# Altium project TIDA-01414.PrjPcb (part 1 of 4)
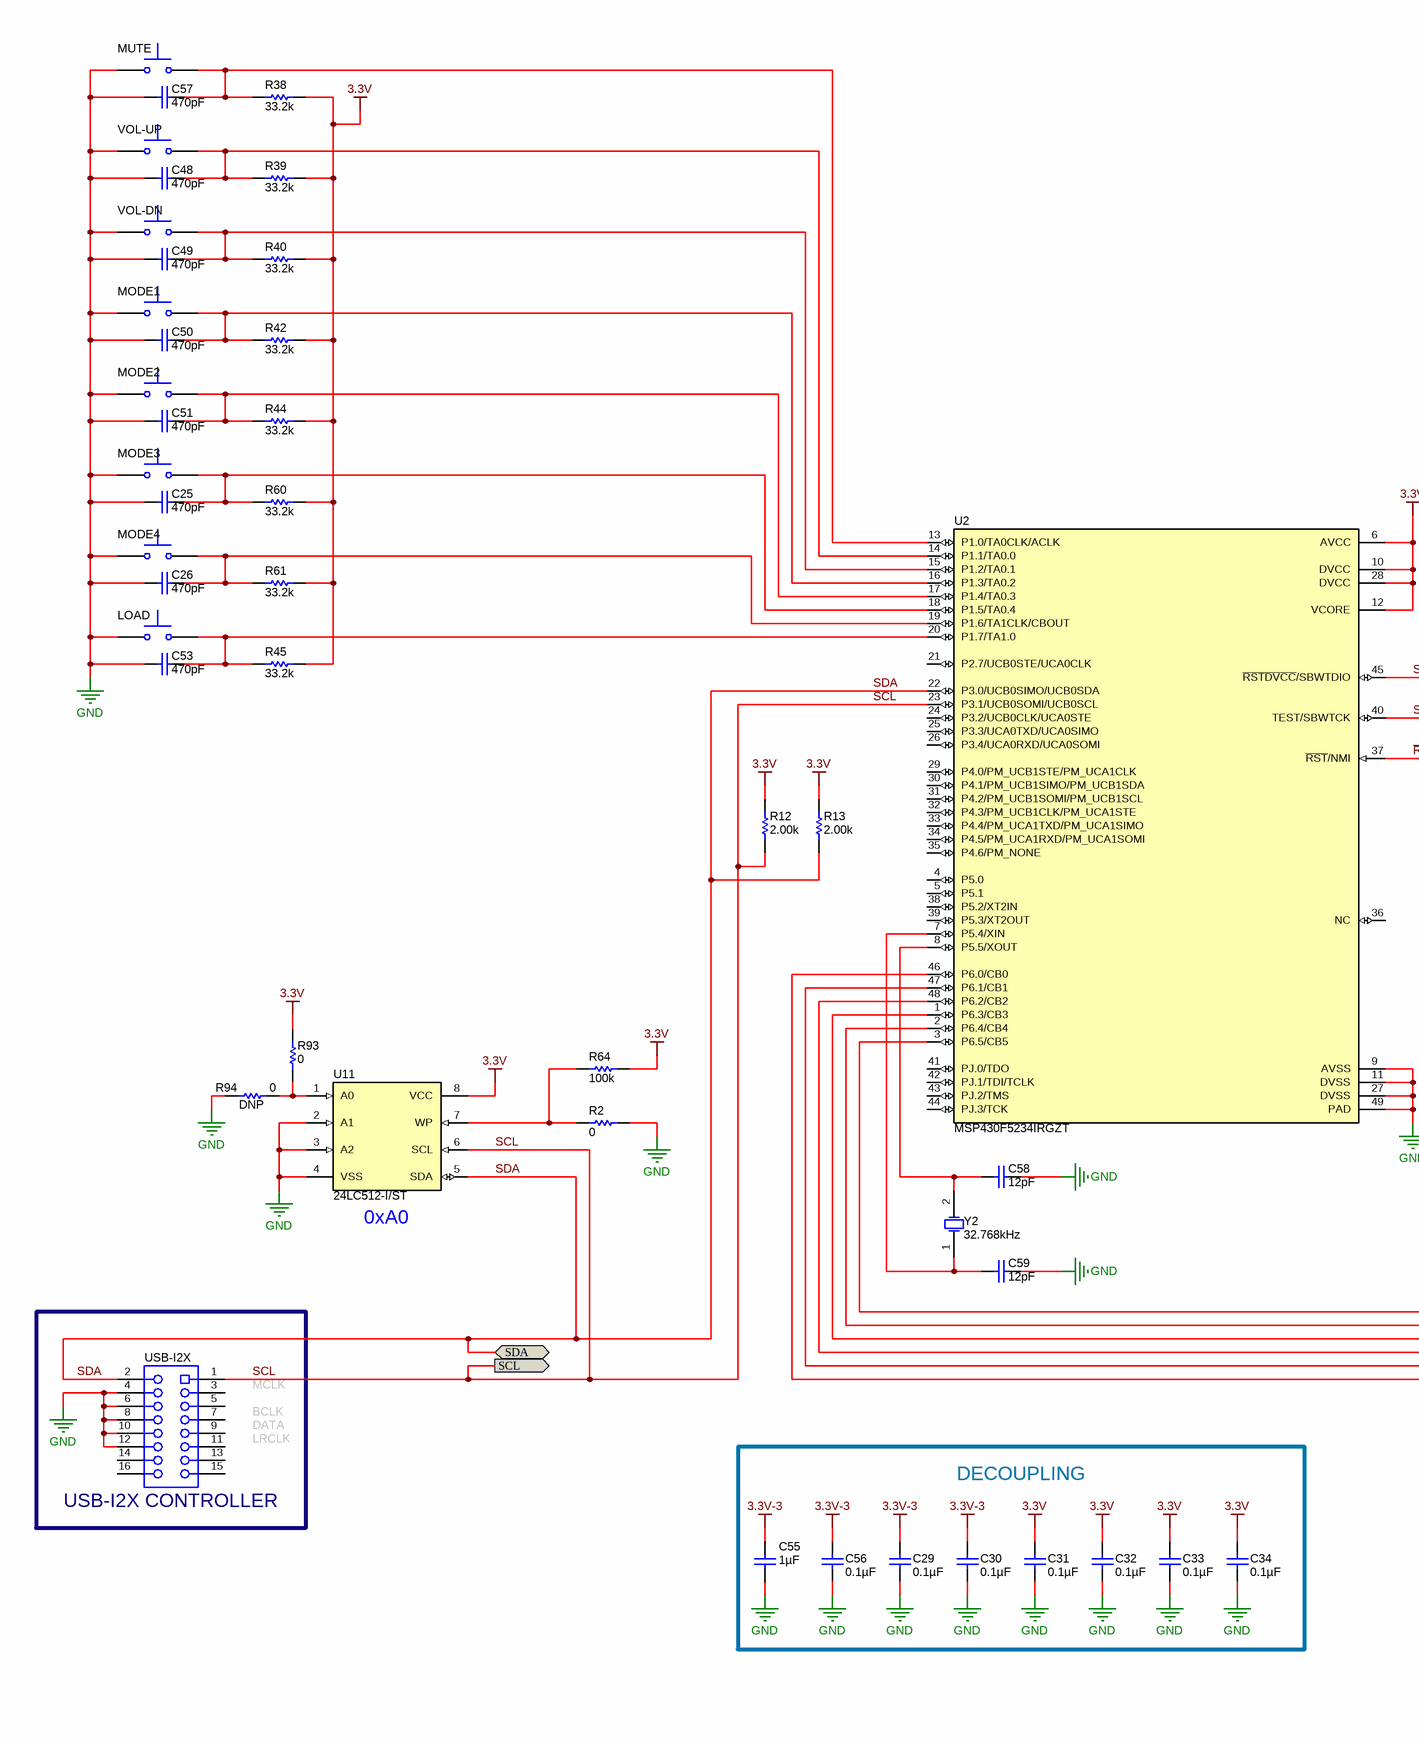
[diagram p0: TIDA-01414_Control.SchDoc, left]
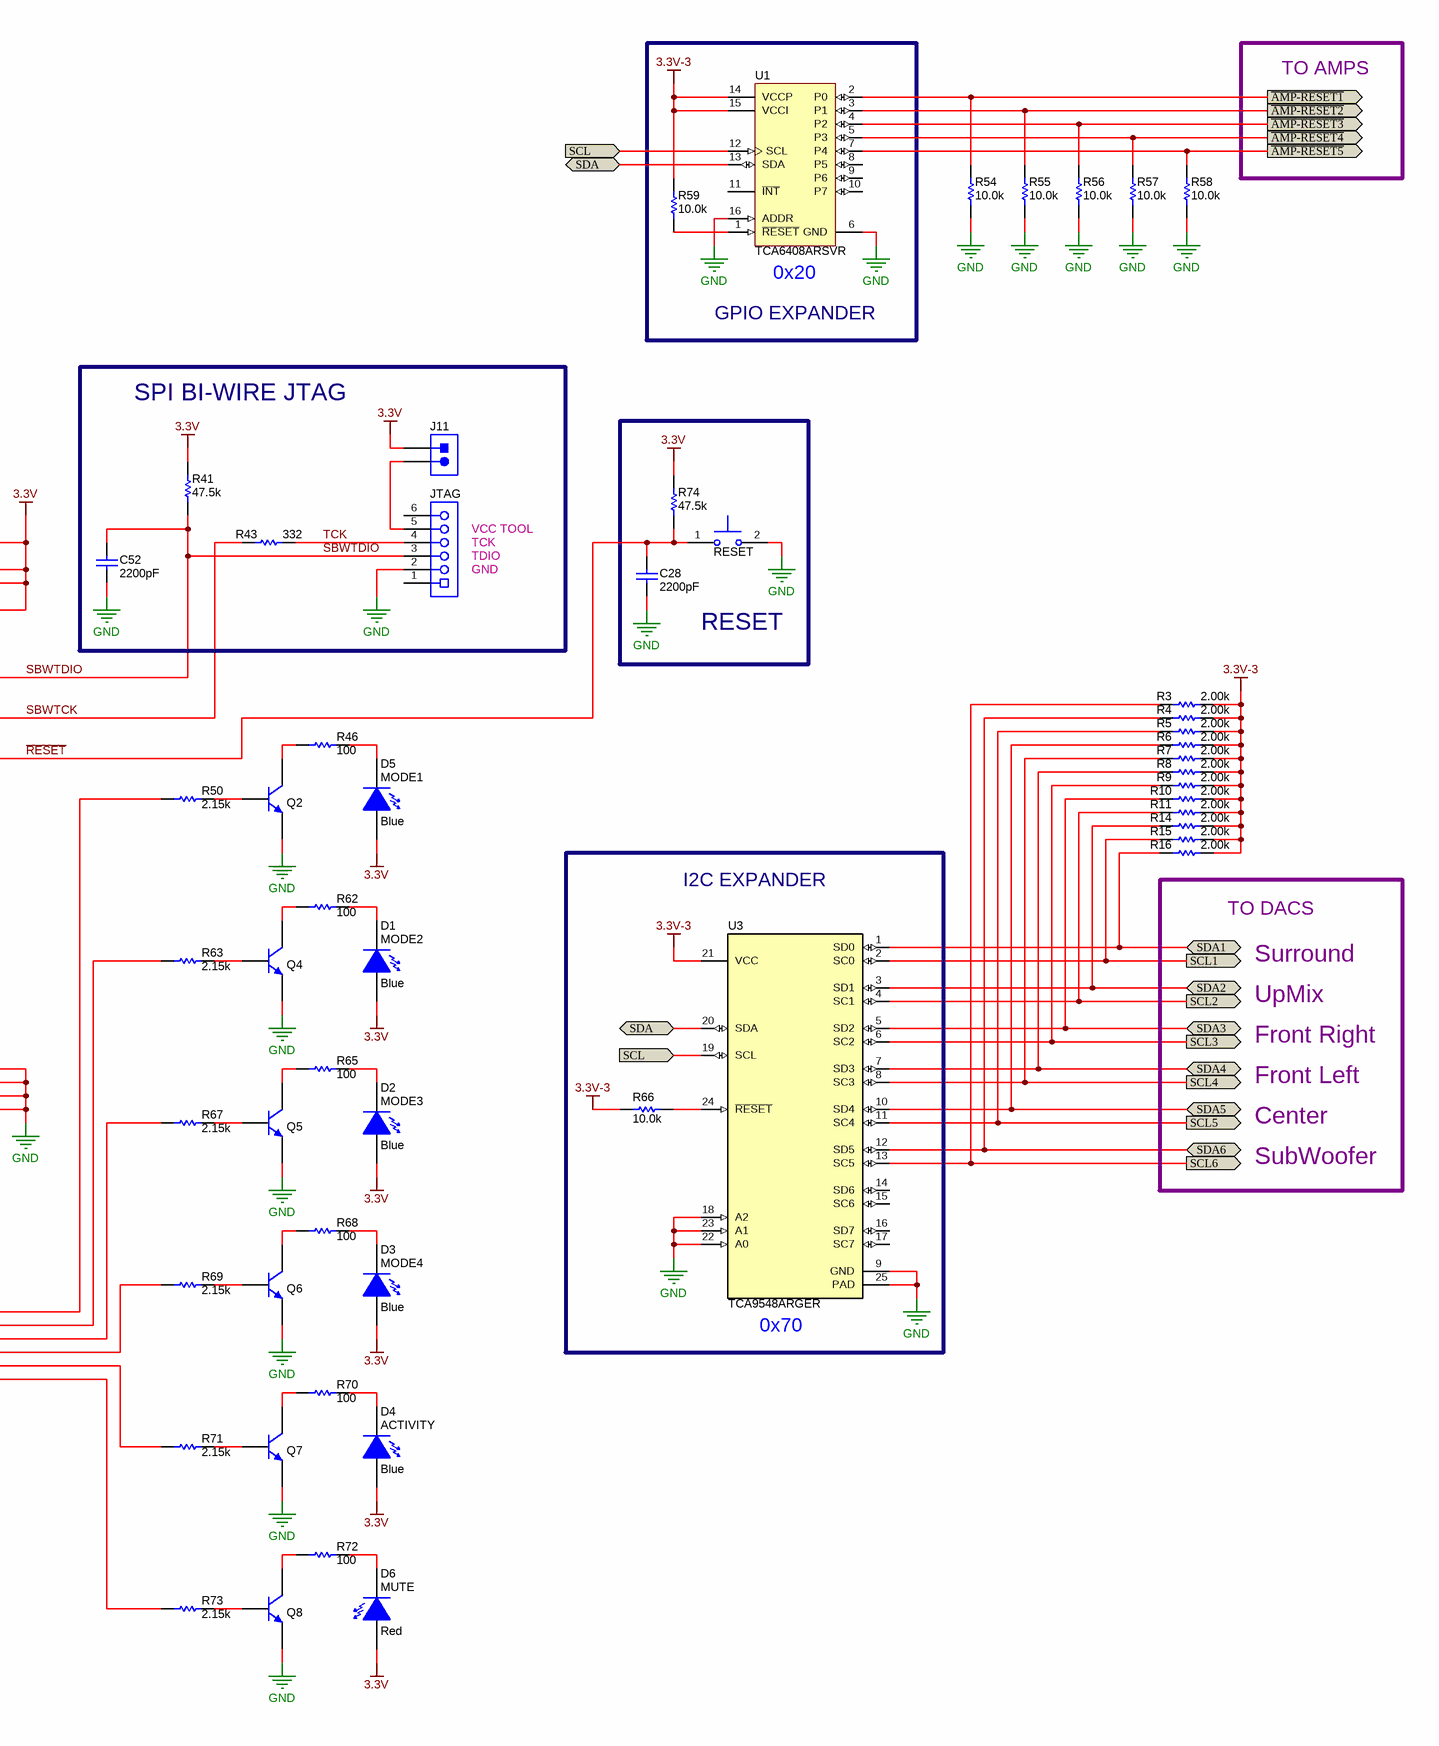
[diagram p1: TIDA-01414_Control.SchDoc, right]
CopyrightYear: 2017; EVM_Orderable: NA; PCB_Layout: LDN; PCB_Rev: E1; PRJ_Customer: Public Release; PRJ_Engineer: MATT BEARDSWORTH; PRJ_Number: TIDA-01414; PRJ_Title: TPA3244 Dolby Atmos SoundBar Reference Design; SCH_Rev: E1; TechSupport: http://www.ti.com/support; TID: TIDA-01414
12 sheets, 841 parts. Net scope: flat (ports and power ports of the same name join across sheets).
Board file: TIDA-01414.PcbDoc
Sheets:
  TIDA-01414_Control.SchDoc
  TIDA-01414_ClockDrivers.SchDoc
  TIDA-01414_SurroundChannel.SchDoc
  TIDA-01414_UpChannel.SchDoc
  TIDA-01414_FrontRightChannel.SchDoc
  TIDA-01414_FrontLeftChannel.SchDoc
  TIDA-01414_CenterChannel.SchDoc
  TIDA-01414_SubWooferChannel.SchDoc
  TIDA-01414_PowerSupplies.SchDoc
  TIDA-01414_Analog-Input_DaughterCard.SchDoc
  TIDA-01414_TID_Hardware.SchDoc
  TIDA-01414_CableAssemblies.SchDoc

## Sheet TIDA-01414_Control.SchDoc: MSP540 IO
size 538 x 342 mm; Date: Not shown in title block; ApprovedBy: Not shown in title block; CheckedBy: Not shown in title block; Author: Not shown in title block; CompanyName: Not shown in title block; DrawnBy: LDN; Engineer: Not shown in title block; Organization: Not shown in title block; Address1: Not shown in title block; Address2: Not shown in title block; Address3: Not shown in title block; Address4: Not shown in title block; DocumentNumber: 1; Revision: Use project parameter SCH_Rev; SheetNumber: 1; SheetTotal: 12; PageSetup: Record=PageOptions¦CenterHorizontal=True¦CenterVertical=True¦PrintScale=1.00¦XCorrection=1.00¦YCorrection=1.00¦PrintKind=0¦BorderSize=5000000¦LeftOffset=0¦BottomOffset=0¦Orientation=2¦PaperLength=1000¦PaperWidth=1000¦Scale=100¦PaperSource=15¦PrintQuality=600¦MediaType=1¦DitherType=10¦PaperKind=Letter¦PrintScaleMode=1

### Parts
C25  ValueDisplayed: 470pF  [0402L]  (hidden comment: GRM1555C1E471JA01D)
C26  ValueDisplayed: 470pF  [0402L]  (hidden comment: GRM1555C1E471JA01D)
C28  ValueDisplayed: 2200pF  [0603L]  (hidden comment: 885012206036)
C29  ValueDisplayed: 0.1µF  [0402L]  (hidden comment: GRM155R71A104KA01D)
C30  ValueDisplayed: 0.1µF  [0402L]  (hidden comment: GRM155R71A104KA01D)
C31  ValueDisplayed: 0.1µF  [0402L]  (hidden comment: GRM155R71A104KA01D)
C32  ValueDisplayed: 0.1µF  [0402L]  (hidden comment: GRM155R71A104KA01D)
C33  ValueDisplayed: 0.1µF  [0402L]  (hidden comment: GRM155R71A104KA01D)
C34  ValueDisplayed: 0.1µF  [0402L]  (hidden comment: GRM155R71A104KA01D)
C48  ValueDisplayed: 470pF  [0402L]  (hidden comment: GRM1555C1E471JA01D)
C49  ValueDisplayed: 470pF  [0402L]  (hidden comment: GRM1555C1E471JA01D)
C50  ValueDisplayed: 470pF  [0402L]  (hidden comment: GRM1555C1E471JA01D)
C51  ValueDisplayed: 470pF  [0402L]  (hidden comment: GRM1555C1E471JA01D)
C52  ValueDisplayed: 2200pF  [0603L]  (hidden comment: 885012206036)
C53  ValueDisplayed: 470pF  [0402L]  (hidden comment: GRM1555C1E471JA01D)
C55  ValueDisplayed: 1µF  [0402L]  (hidden comment: C1005X5R0J105M050BB)
C56  ValueDisplayed: 0.1µF  [0402L]  (hidden comment: GRM155R71A104KA01D)
C57  ValueDisplayed: 470pF  [0402L]  (hidden comment: GRM1555C1E471JA01D)
C58  ValueDisplayed: 12pF  [0402L]  (hidden comment: GRM1555C1H120JA01D)
C59  ValueDisplayed: 12pF  [0402L]  (hidden comment: GRM1555C1H120JA01D)
D1  MODE2  value Blue  [LED_SMLP12_BLUE]
D2  MODE3  value Blue  [LED_SMLP12_BLUE]
D3  MODE4  value Blue  [LED_SMLP12_BLUE]
D4  ACTIVITY  value Blue  [LED_SMLP12_BLUE]
D5  MODE1  value Blue  [LED_SMLP12_BLUE]
D6  MUTE  value Red  [LED_LTST-C190_Red]
J11  PBC02SAAN  [Sullins_PBC02SAAN]  (value not drawn)
JTAG  851-43-006-10-001000  [Mill-Max_851-XX-006-10-001000]  (value not drawn)
LOAD  (no value)  [SW_TL1015AF160QG]
MODE1  (no value)  [SW_TL1015AF160QG]
MODE2  (no value)  [SW_TL1015AF160QG]
MODE3  (no value)  [SW_TL1015AF160QG]
MODE4  (no value)  [SW_TL1015AF160QG]
MUTE  (no value)  [SW_TL1015AF160QG]
Q2  MMBT2222A  [SOT-23]  (value not drawn)
Q4  MMBT2222A  [SOT-23]  (value not drawn)
Q5  MMBT2222A  [SOT-23]  (value not drawn)
Q6  MMBT2222A  [SOT-23]  (value not drawn)
Q7  MMBT2222A  [SOT-23]  (value not drawn)
Q8  MMBT2222A  [SOT-23]  (value not drawn)
R2  ValueDisplayed: 0  [0603L]  (hidden comment: CRCW06030000Z0EA)
R3  ValueDisplayed: 2.00k  [0402L]  (hidden comment: ERJ-2RKF2001X)
R4  ValueDisplayed: 2.00k  [0402L]  (hidden comment: ERJ-2RKF2001X)
R5  ValueDisplayed: 2.00k  [0402L]  (hidden comment: ERJ-2RKF2001X)
R6  ValueDisplayed: 2.00k  [0402L]  (hidden comment: ERJ-2RKF2001X)
R7  ValueDisplayed: 2.00k  [0402L]  (hidden comment: ERJ-2RKF2001X)
R8  ValueDisplayed: 2.00k  [0402L]  (hidden comment: ERJ-2RKF2001X)
R9  ValueDisplayed: 2.00k  [0402L]  (hidden comment: ERJ-2RKF2001X)
R10  ValueDisplayed: 2.00k  [0402L]  (hidden comment: ERJ-2RKF2001X)
R11  ValueDisplayed: 2.00k  [0402L]  (hidden comment: ERJ-2RKF2001X)
R12  ValueDisplayed: 2.00k  [0402L]  (hidden comment: ERJ-2RKF2001X)
R13  ValueDisplayed: 2.00k  [0402L]  (hidden comment: ERJ-2RKF2001X)
R14  ValueDisplayed: 2.00k  [0402L]  (hidden comment: ERJ-2RKF2001X)
R15  ValueDisplayed: 2.00k  [0402L]  (hidden comment: ERJ-2RKF2001X)
R16  ValueDisplayed: 2.00k  [0402L]  (hidden comment: ERJ-2RKF2001X)
R38  ValueDisplayed: 33.2k  [0402L]  (hidden comment: CRCW040233K2FKED)
R39  ValueDisplayed: 33.2k  [0402L]  (hidden comment: CRCW040233K2FKED)
R40  ValueDisplayed: 33.2k  [0402L]  (hidden comment: CRCW040233K2FKED)
R41  ValueDisplayed: 47.5k  [0402L]  (hidden comment: CRCW040247K5FKED)
R42  ValueDisplayed: 33.2k  [0402L]  (hidden comment: CRCW040233K2FKED)
R43  ValueDisplayed: 332  [0402L]  (hidden comment: CRCW0402332RFKED)
R44  ValueDisplayed: 33.2k  [0402L]  (hidden comment: CRCW040233K2FKED)
R45  ValueDisplayed: 33.2k  [0402L]  (hidden comment: CRCW040233K2FKED)
R46  ValueDisplayed: 100  [0402L]  (hidden comment: ERJ-2RKF1000X)
R50  ValueDisplayed: 2.15k  [0402L]  (hidden comment: CRCW04022K15FKED)
R54  ValueDisplayed: 10.0k  [0603L]  (hidden comment: CRCW060310K0FKEA)
R55  ValueDisplayed: 10.0k  [0603L]  (hidden comment: CRCW060310K0FKEA)
R56  ValueDisplayed: 10.0k  [0603L]  (hidden comment: CRCW060310K0FKEA)
R57  ValueDisplayed: 10.0k  [0603L]  (hidden comment: CRCW060310K0FKEA)
R58  ValueDisplayed: 10.0k  [0603L]  (hidden comment: CRCW060310K0FKEA)
R59  value 10.0k  [0402L]  (hidden comment: CRCW040210K0FKED)
R60  ValueDisplayed: 33.2k  [0402L]  (hidden comment: CRCW040233K2FKED)
R61  ValueDisplayed: 33.2k  [0402L]  (hidden comment: CRCW040233K2FKED)
R62  ValueDisplayed: 100  [0402L]  (hidden comment: ERJ-2RKF1000X)
R63  ValueDisplayed: 2.15k  [0402L]  (hidden comment: CRCW04022K15FKED)
R64  value 100k  [0402L]  (hidden comment: CRCW0402100KFKED)
R65  ValueDisplayed: 100  [0402L]  (hidden comment: ERJ-2RKF1000X)
R66  ValueDisplayed: 10.0k  [0603L]  (hidden comment: CRCW060310K0FKEA)
R67  ValueDisplayed: 2.15k  [0402L]  (hidden comment: CRCW04022K15FKED)
R68  ValueDisplayed: 100  [0402L]  (hidden comment: ERJ-2RKF1000X)
R69  ValueDisplayed: 2.15k  [0402L]  (hidden comment: CRCW04022K15FKED)
R70  ValueDisplayed: 100  [0402L]  (hidden comment: ERJ-2RKF1000X)
R71  ValueDisplayed: 2.15k  [0402L]  (hidden comment: CRCW04022K15FKED)
R72  ValueDisplayed: 100  [0402L]  (hidden comment: ERJ-2RKF1000X)
R73  ValueDisplayed: 2.15k  [0402L]  (hidden comment: CRCW04022K15FKED)
R74  ValueDisplayed: 47.5k  [0402L]  (hidden comment: CRCW040247K5FKED)
R93  ValueDisplayed: 0  [0603L]  (hidden comment: CRCW06030000Z0EA)
R94  DNP  ValueDisplayed: 0  [0603L]
RESET  TL1015AF160QG  [SW_TL1015AF160QG]  (value not drawn)
U1  TCA6408ARSVR  [RSV0016A]
U2  MSP430F5234IRGZT  [RGZ0048B]
U3  TCA9548ARGER  [RGE0024C]
U11  24LC512-I/ST  [TSSOP-8]
USB-I2X  PPPC082LFBN-RC  [Sullins_xPxC082LFBN]  (value not drawn)
VOL-DN  (no value)  [SW_TL1015AF160QG]
VOL-UP  (no value)  [SW_TL1015AF160QG]
Y2  Frequency: 32.768kHz  [XTAL_NX3215SA]  (hidden comment: NX3215SA-32.768K-STD-MUA-8)

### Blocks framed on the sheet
SPI BI-WIRE JTAG: C52 J11 JTAG R41 R43
RESET: C28 R74 RESET
USB-I2X CONTROLLER: USB-I2X
DECOUPLING: C29-C34 C55 C56

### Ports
SCL1 (out), SCL2 (out), SCL3 (out), SCL4 (out), SCL5 (out), SCL6 (out), SCL (in), SCL (out), SDA1 (bidir), SDA2 (bidir), SDA3 (bidir), SDA4 (bidir), SDA5 (bidir), SDA6 (bidir), SDA (bidir), ~{AMP-RESET1} (out), ~{AMP-RESET2} (out), ~{AMP-RESET3} (out), ~{AMP-RESET4} (out), ~{AMP-RESET5} (out)

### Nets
3.3V: C31.2 C32.2 C33.2 C34.2 D1.1(A) D2.1(A) D3.1(A) D4.1(A) D5.1(A) D6.1(A) J11.1 R12.1 R13.1 R38.1 R39.1 R40.1 R41.2 R42.1 R44.1 R45.1 R60.1 R61.1 R64.2 R74.2 R93.2 U2.6(AVCC) U2.10(DVCC) U2.12(VCORE) U2.28(DVCC) U11.8(VCC)
3.3V-3: C29.2 C30.2 C55.2 C56.2 R3.2 R4.2 R5.2 R6.2 R7.2 R8.2 R9.2 R10.2 R11.2 R14.2 R15.2 R16.2 R59.1 R66.2 U1.14(VCCP) U1.15(VCCI) U3.21(VCC)
GND: C25.2 C26.2 C28.1 C29.1 C30.1 C31.1 C32.1 C33.1 C34.1 C48.2 C49.2 C50.2 C51.2 C52.1 C53.2 C55.1 C56.1 C57.2 C58.1 C59.1 JTAG.2 LOAD.1 MODE1.1 MODE2.1 MODE3.1 MODE4.1 MUTE.1 Q2.2(E) Q4.2(E) Q5.2(E) Q6.2(E) Q7.2(E) Q8.2(E) R2.2 R54.2 R55.2 R56.2 R57.2 R58.2 R94.2 RESET.2 U1.6(GND) U1.16(ADDR) U2.9(AVSS) U2.11(DVSS) U2.27(DVSS) U2.49(PAD) U3.9(GND) U3.18(A2) U3.22(A0) U3.23(A1) U3.25(PAD) U11.2(A1) U11.3(A2) U11.4(VSS) USB-I2X.4 USB-I2X.6 USB-I2X.8 USB-I2X.10 USB-I2X.12 VOL-DN.1 VOL-UP.1
~{AMP-RESET1}: R54.1 U1.2(P0) ; port ~{AMP-RESET1}
~{AMP-RESET2}: R55.1 U1.3(P1) ; port ~{AMP-RESET2}
~{AMP-RESET3}: R56.1 U1.4(P2) ; port ~{AMP-RESET3}
~{AMP-RESET4}: R57.1 U1.5(P3) ; port ~{AMP-RESET4}
~{AMP-RESET5}: R58.1 U1.7(P4) ; port ~{AMP-RESET5}
~{RESET}: C28.2 R74.1 RESET.1 U2.37(~{RST}/NMI)
SBWTCK: R43.1 U2.40(TEST/SBWTCK)
SBWTDIO: C52.2 JTAG.3 R41.1 U2.45(~{RSTDVCC}/SBWTDIO)
SCL: R12.2 U1.12(SCL) U2.23(P3.1/UCB0SOMI/UCB0SCL) U3.19(SCL) U11.6(SCL) USB-I2X.1 ; port SCL
SCL1: R15.1 U3.2(SC0) ; port SCL1
SCL2: R11.1 U3.4(SC1) ; port SCL2
SCL3: R9.1 U3.6(SC2) ; port SCL3
SCL4: R7.1 U3.8(SC3) ; port SCL4
SCL5: R5.1 U3.11(SC4) ; port SCL5
SCL6: R3.1 U3.13(SC5) ; port SCL6
SDA: R13.2 U1.13(SDA) U2.22(P3.0/UCB0SIMO/UCB0SDA) U3.20(SDA) U11.5(SDA) USB-I2X.2 ; port SDA
SDA1: R16.1 U3.1(SD0) ; port SDA1
SDA2: R14.1 U3.3(SD1) ; port SDA2
SDA3: R10.1 U3.5(SD2) ; port SDA3
SDA4: R8.1 U3.7(SD3) ; port SDA4
SDA5: R6.1 U3.10(SD4) ; port SDA5
SDA6: R4.1 U3.12(SD5) ; port SDA6
TCK: JTAG.4 R43.2
NetC25_1: C25.1 MODE3.2 R60.2 U2.18(P1.5/TA0.4)
NetC26_1: C26.1 MODE4.2 R61.2 U2.19(P1.6/TA1CLK/CBOUT)
NetC48_1: C48.1 R39.2 U2.14(P1.1/TA0.0) VOL-UP.2
NetC49_1: C49.1 R40.2 U2.15(P1.2/TA0.1) VOL-DN.2
NetC50_1: C50.1 MODE1.2 R42.2 U2.16(P1.3/TA0.2)
NetC51_1: C51.1 MODE2.2 R44.2 U2.17(P1.4/TA0.3)
NetC53_1: C53.1 LOAD.2 R45.2 U2.20(P1.7/TA1.0)
NetC57_1: C57.1 MUTE.2 R38.2 U2.13(P1.0/TA0CLK/ACLK)
NetC58_2: C58.2 U2.8(P5.5/XOUT) Y2.2(OSC2)
NetC59_2: C59.2 U2.7(P5.4/XIN) Y2.1(OSC1)
NetD1_2: D1.2(K) R62.1
NetD2_2: D2.2(K) R65.1
NetD3_2: D3.2(K) R68.1
NetD4_2: D4.2(K) R70.1
NetD5_2: D5.2(K) R46.1
NetD6_2: D6.2(K) R72.1
NetJ11_2: J11.2 JTAG.5
NetQ2_1: Q2.1(B) R50.1
NetQ2_3: Q2.3(C) R46.2
NetQ4_1: Q4.1(B) R63.1
NetQ4_3: Q4.3(C) R62.2
NetQ5_1: Q5.1(B) R67.1
NetQ5_3: Q5.3(C) R65.2
NetQ6_1: Q6.1(B) R69.1
NetQ6_3: Q6.3(C) R68.2
NetQ7_1: Q7.1(B) R71.1
NetQ7_3: Q7.3(C) R70.2
NetQ8_1: Q8.1(B) R73.1
NetQ8_3: Q8.3(C) R72.2
NetR2_1: R2.1 R64.1 U11.7(WP)
NetR50_2: R50.2 U2.3(P6.5/CB5)
NetR59_2: R59.2 U1.1(~{RESET})
NetR63_2: R63.2 U2.2(P6.4/CB4)
NetR66_1: R66.1 U3.24(~{RESET})
NetR67_2: R67.2 U2.1(P6.3/CB3)
NetR69_2: R69.2 U2.48(P6.2/CB2)
NetR71_2: R71.2 U2.47(P6.1/CB1)
NetR73_2: R73.2 U2.46(P6.0/CB0)
NetR93_1: R93.1 R94.1 U11.1(A0)

Not connected (* = marked no-connect by the designer): JTAG 1 6; U1 8(P5) 9(P6) 10(P7) 11(~{INT}); U2 4(P5.0) 5(P5.1) 21(P2.7/UCB0STE/UCA0CLK) 24(P3.2/UCB0CLK/UCA0STE) 25(P3.3/UCA0TXD/UCA0SIMO) 26(P3.4/UCA0RXD/UCA0SOMI) 29(P4.0/PM_UCB1STE/PM_UCA1CLK) 30(P4.1/PM_UCB1SIMO/PM_UCB1SDA) 31(P4.2/PM_UCB1SOMI/PM_UCB1SCL) 32(P4.3/PM_UCB1CLK/PM_UCA1STE) 33(P4.4/PM_UCA1TXD/PM_UCA1SIMO) 34(P4.5/PM_UCA1RXD/PM_UCA1SOMI) 35(P4.6/PM_NONE) 36(NC) 38(P5.2/XT2IN) 39(P5.3/XT2OUT) 41(PJ.0/TDO) 42(PJ.1/TDI/TCLK) 43(PJ.2/TMS) 44(PJ.3/TCK); U3 14(SD6) 15(SC6) 16(SD7) 17(SC7); USB-I2X 3 5 7 9 11 13 14 15 16

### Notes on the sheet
- TO AMPS
- (near U1) 0x20
- GPIO EXPANDER
- (near JTAG) VCC TOOL
- (near JTAG) TCK
- (near JTAG) TDIO
- (near JTAG) GND
- I2C EXPANDER
- TO DACS
- Surround
- UpMix
- Front Right
- Front Left
- Center
- SubWoofer
- (near U11) 0xA0
- (near U3) 0x70
- MCLK
- BCLK
- DATA
- LRCLK

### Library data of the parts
C25 C26 C48-C51 C53 C57 = GRM1555C1E471JA01D: CAP, CERM, 470 pF, 25 V, +/- 5%, C0G/NP0, 0402; Manufacturer: MuRata; Polarized: N; CompType: Capacitor; Value: 470pF; U/M: EA; Cap_F: 0.00000000047; Tolerance_%: 5; Value1: Unknown; VDC_V: 25; Value2: 25V; TaMin_C: -55; TaMax_C: 125; Cap_Case: 0402; AEC Category: Q200; SizeArea_mm2: 0.5; SizeAreaWB_mm2: 3; SizeX_mm: 1; SizeZ_mm: 0.6
C28 C52 = 885012206036: CAP, CERM, 2200 pF, 16 V, +/- 10%, X7R, 0603; Manufacturer: Wurth Elektronik; Polarized: N; CompType: Capacitor; Value: 2200pF; U/M: EA; Cap_F: 0.0000000022; Tolerance_%: 10; Value1: Unknown; VDC_V: 16; Value2: 16V; TaMin_C: -55; TaMax_C: 125; Cap_Case: 0603; AEC Category: Q200; SizeArea_mm2: 1.28; SizeAreaWB_mm2: 4.68; SizeX_mm: 1.6; SizeY_mm: 0.8; SizeZ_mm: 1
C29-C34 C56 = GRM155R71A104KA01D: CAP, CERM, 0.1 µF, 10 V, +/- 10%, X7R, 0402; Manufacturer: MuRata; Polarized: N; CompType: Capacitor; Value: 0.1uF; U/M: EA; Cap_F: 0.0000001; Tolerance_%: 10; Value1: Unknown; Value2: 10V; TaMin_C: -55; TaMax_C: 125; Cap_Case: 0402; AEC Category: Q200
C55 = C1005X5R0J105M050BB: CAP, CERM, 1 µF, 6.3 V, +/- 20%, X5R, 0402; Manufacturer: TDK; Polarized: N; CompType: Capacitor; Value: 1uF; U/M: EA; Cap_F: 0.000001; Tolerance_%: 20; ESR_ohm: 0.0079; Value1: 0.0079 ohm; VDC_V: 6.3; Value2: 6.3V; TaMin_C: -55; TaMax_C: 85; Cap_Case: 0402; SizeArea_mm2: 0.5; SizeAreaWB_mm2: 3; SizeX_mm: 1; SizeZ_mm: 0.6; AEC Category: Q200
C58 C59 = GRM1555C1H120JA01D: CAP, CERM, 12 pF, 50 V, +/- 5%, C0G/NP0, 0402; Manufacturer: MuRata; Polarized: N; CompType: Capacitor; Value: 12pF; U/M: EA; Cap_F: 0.000000000012; Tolerance_%: 5; Value1: Unknown; VDC_V: 50; Value2: 50V; TaMin_C: -55; TaMax_C: 125; Cap_Case: 0402; AEC Category: Q200; SizeArea_mm2: 0.5; SizeAreaWB_mm2: 3; SizeX_mm: 1; SizeZ_mm: 0.6
D1-D5 = SMLP12BC7TT86: LED, Blue, SMD; Manufacturer: Rohm; Type: InGaN; Vf_V: 2.9; Value2: 2.9V; Io_A: 0.005; Tjmax_C: 85; Value1: W; U/M: EA
D6 = LTST-C190CKT: LED, Red, SMD; Manufacturer: Lite-On; Vf_V: 2; Value2: 2V; Io_A: 0.02; Tjmax_C: 85; Power_TotalModule: 0.0625; Value1: 0.0625W; U/M: EA
J11 = PBC02SAAN: Header, 100mil, 2x1, Gold, TH; Manufacturer: Sullins Connector Solutions; SymbolCreator: a0412235; Pitch_mm: 2.54; Gender: Male; Shrouded: N; Row_Count: 1; Current_A: 3; Voltage_V: 1800; Cert_UL: Y
JTAG = 851-43-006-10-001000: Receptacle, 50mil, 6x1, Gold, TH; Manufacturer: Mill-Max; SymbolCreator: a0411947
LOAD MODE1-MODE4 MUTE RESET VOL-DN VOL-UP = TL1015AF160QG: Switch, Tactile, SPST-NO, 0.05A, 12V, SMT; Manufacturer: E-Switch; SymbolCreator: a0412235; VDC_V: 12; SwitchFunction: Off-Mom; PositionCount: 1; CurrentRating_mA: 50
Q2 Q4-Q8 = MMBT2222A, Fairchild Semiconductor: Transistor, NPN, 40 V, 0.15 A, SOT-23; CompType: BJT; PNP: 0; NPN: 1; Vceo_V: 40; Vcesat1_V: 0.3; Value: 40 V; IcRated_A: 0.15; Value1: 0.15 A; HfeMax: 300; TaMin_C: -55; TaMax_C: 150; U/M: EA; AEC Category: Q101
R2 R93 R94 = CRCW06030000Z0EA: RES, 0, 5%, 0.1 W, 0603; Manufacturer: Vishay-Dale; CompType: Resistor; Value: 0; Value_Code: 0000; Tolerance_%: 5; Power_W: 0.1; Value2: 0.1W; VDC_V: 75; TempCo: 200 ppm/C; EIA_Code: E24; U/M: EA; AEC Category: Q200
R3-R16 = ERJ-2RKF2001X: RES, 2.00 k, 1%, 0.1 W, AEC-Q200 Grade 0, 0402; Manufacturer: Panasonic; CompType: Resistor; Value: 2.00k; Res_ohm: 2000; Value_Code: 2k00; Tolerance_%: 1; Power_W: 0.1; Value2: 0.1W; VDC_V: 50; TempCo: 100 ppm/C; EIA_Code: E96; U/M: EA; AEC Category: Q200; AEC Qualified: Y; AEC Grade: 0; SizeArea_mm2: 0.5; SizeZ_mm: 0.6
R38-R40 R42 R44 R45 R60 R61 = CRCW040233K2FKED: RES, 33.2 k, 1%, 0.063 W, 0402; Manufacturer: Vishay-Dale; CompType: Resistor; Value: 33.2k; Res_ohm: 33200; Value_Code: 33k2; Tolerance_%: 1; Power_W: 0.063; Value2: 0.063W; VDC_V: 50; TempCo: 100 ppm/C; SizeArea_mm2: 0.5; SizeZ_mm: 0.6; EIA_Code: E96; U/M: EA; AEC Category: Q200
R41 R74 = CRCW040247K5FKED: RES, 47.5 k, 1%, 0.063 W, 0402; Manufacturer: Vishay-Dale; CompType: Resistor; Value: 47.5k; Res_ohm: 47500; Value_Code: 47k5; Tolerance_%: 1; Power_W: 0.063; Value2: 0.063W; VDC_V: 50; TempCo: 100 ppm/C; SizeArea_mm2: 0.5; SizeZ_mm: 0.6; EIA_Code: E96; U/M: EA; AEC Category: Q200
R43 = CRCW0402332RFKED: RES, 332, 1%, 0.063 W, 0402; Manufacturer: Vishay-Dale; CompType: Resistor; Value: 332; Value_Code: 332R; Tolerance_%: 1; Power_W: 0.063; Value2: 0.063W; VDC_V: 50; TempCo: 100 ppm/C; SizeArea_mm2: 0.5; SizeZ_mm: 0.6; EIA_Code: E96; U/M: EA; AEC Category: Q200
R46 R62 R65 R68 R70 R72 = ERJ-2RKF1000X: RES, 100, 1%, 0.1 W, 0402; Manufacturer: Panasonic; CompType: Resistor; Value: 100; Value_Code: 100R; Tolerance_%: 1; Power_W: 0.1; Value2: 0.1W; VDC_V: 50; TempCo: 100 ppm/C; EIA_Code: E96; U/M: EA; AEC Category: Q200; SizeArea_mm2: 0.5; SizeZ_mm: 0.6
R50 R63 R67 R69 R71 R73 = CRCW04022K15FKED: RES, 2.15 k, 1%, 0.063 W, 0402; Manufacturer: Vishay-Dale; CompType: Resistor; Value: 2.15k; Res_ohm: 2150; Value_Code: 2k15; Tolerance_%: 1; Power_W: 0.063; Value2: 0.063W; VDC_V: 50; TempCo: 100 ppm/C; EIA_Code: E96; U/M: EA; AEC Category: Q200; SizeArea_mm2: 0.5; SizeZ_mm: 0.6
R54-R58 R66 = CRCW060310K0FKEA: RES, 10.0 k, 1%, 0.1 W, 0603; Manufacturer: Vishay-Dale; CompType: Resistor; Value: 10.0k; Res_ohm: 10000; Value_Code: 10k0; Tolerance_%: 1; Power_W: 0.1; Value2: 0.1W; VDC_V: 75; TempCo: 100 ppm/C; EIA_Code: E96; U/M: EA; AEC Category: Q200
R59 = CRCW040210K0FKED: RES, 10.0k ohm, 1%, 0.063W, 0402; Manufacturer: Vishay-Dale; CompType: Resistor; Res_ohm: 10000; Value_Code: 10k0; Tolerance_%: 1; Power_W: 0.063; VDC_V: 50; TempCo: 100 ppm/C; EIA_Code: E96; U/M: EA
R64 = CRCW0402100KFKED: RES, 100 k, 1%, 0.063 W, 0402; Manufacturer: Vishay-Dale; CompType: Resistor; Res_ohm: 100000; Tolerance_%: 1; Power_W: 0.063; Value2: 0.063W; VDC_V: 50; TempCo: 100 ppm/C; EIA_Code: E96; U/M: EA; AEC Category: Q200
U1 = TCA6408ARSVR: Low-Voltage 8-Bit I2C and SMBus I/O Expander, 1.65 to 5.5 V, -40 to 85 degC, 16-pin UQFN (RSV), Green (RoHS & no Sb/Br); Manufacturer: Texas Instruments; Alternate Manufacturer: None; Alternate PartNumber: Equivalent; SubFamily: I2C IO Expander; No. of Outputs: 8; Interrupt Output: Yes; fSCLK(Max)(MHz): 400; VCC(Min)(V): 1.65; VCC(Max)(V): 5.5; I2C Address: 0100 00x
U2 = MSP430F5234IRGZT: Mixed Signal Microcontroller, RGZ0048B (VQFN-48); Alternate PartNumber: MSP430FR5969IRGZT; Manufacturer: Texas Instruments; SymbolCreator: a0411947; SizeArea_mm2: 49; SizeAreaWB_mm2: 81; SizeX_mm: 7; SizeZ_mm: 1; CompType: IC; U/M: EA
U3 = TCA9548ARGER: 8-Channel I2C Switch With Reset, RGE0024C (VQFN-24); Manufacturer: Texas Instruments; SymbolCreator: x0208326; SizeArea_mm2: 16; SizeAreaWB_mm2: 25; SizeX_mm: 4; SizeZ_mm: 1; CompType: IC; U/M: EA
U11 = 24LC512-I/ST: EEPROM, 512KBIT, 400KHZ, 8TSSOP; Manufacturer: Microchip; SymbolCreator: a0411947; SizeAreaWB_mm2: 42; SizeArea_mm2: 19.2; SizeX_mm: 6.4; SizeY_mm: 3; SizeZ_mm: 1.2
USB-I2X = PPPC082LFBN-RC: Receptacle, 2.54mm, 8x2, Gold, TH; Manufacturer: Sullins Connector Solutions; SymbolCreator: a0411947; Pitch_mm: 2.54; Gender: Female; Row_Count: 2; Current_A: 3; Voltage_V: 250; Cert_UL: Y
Y2 = NX3215SA-32.768K-STD-MUA-8: Crystal, 32.768kHz, 12.5pF, SMD; Manufacturer: NDK; SymbolCreator: a0412235; U/M: EA; TaMin_C: -40; TaMax_C: 85; Frequency Stability: ±20ppm

## Sheet TIDA-01414_ClockDrivers.SchDoc: Main Schematic
size 431 x 279 mm; Date: Not shown in title block; ApprovedBy: Not shown in title block; CheckedBy: Not shown in title block; Author: Not shown in title block; CompanyName: Not shown in title block; DrawnBy: LDN; Engineer: Not shown in title block; Organization: Not shown in title block; Address1: Not shown in title block; Address2: Not shown in title block; Address3: Not shown in title block; Address4: Not shown in title block; DocumentNumber: 2; Revision: Use project parameter SCH_Rev; SheetNumber: 2; SheetTotal: 12; PageSetup: Record=PageOptions¦CenterHorizontal=True¦CenterVertical=True¦PrintScale=1.00¦XCorrection=1.00¦YCorrection=1.00¦PrintKind=0¦BorderSize=5000000¦LeftOffset=0¦BottomOffset=0¦Orientation=2¦PaperLength=1000¦PaperWidth=1000¦Scale=100¦PaperSource=15¦PrintQuality=600¦MediaType=1¦DitherType=10¦PaperKind=Letter¦PrintScaleMode=1
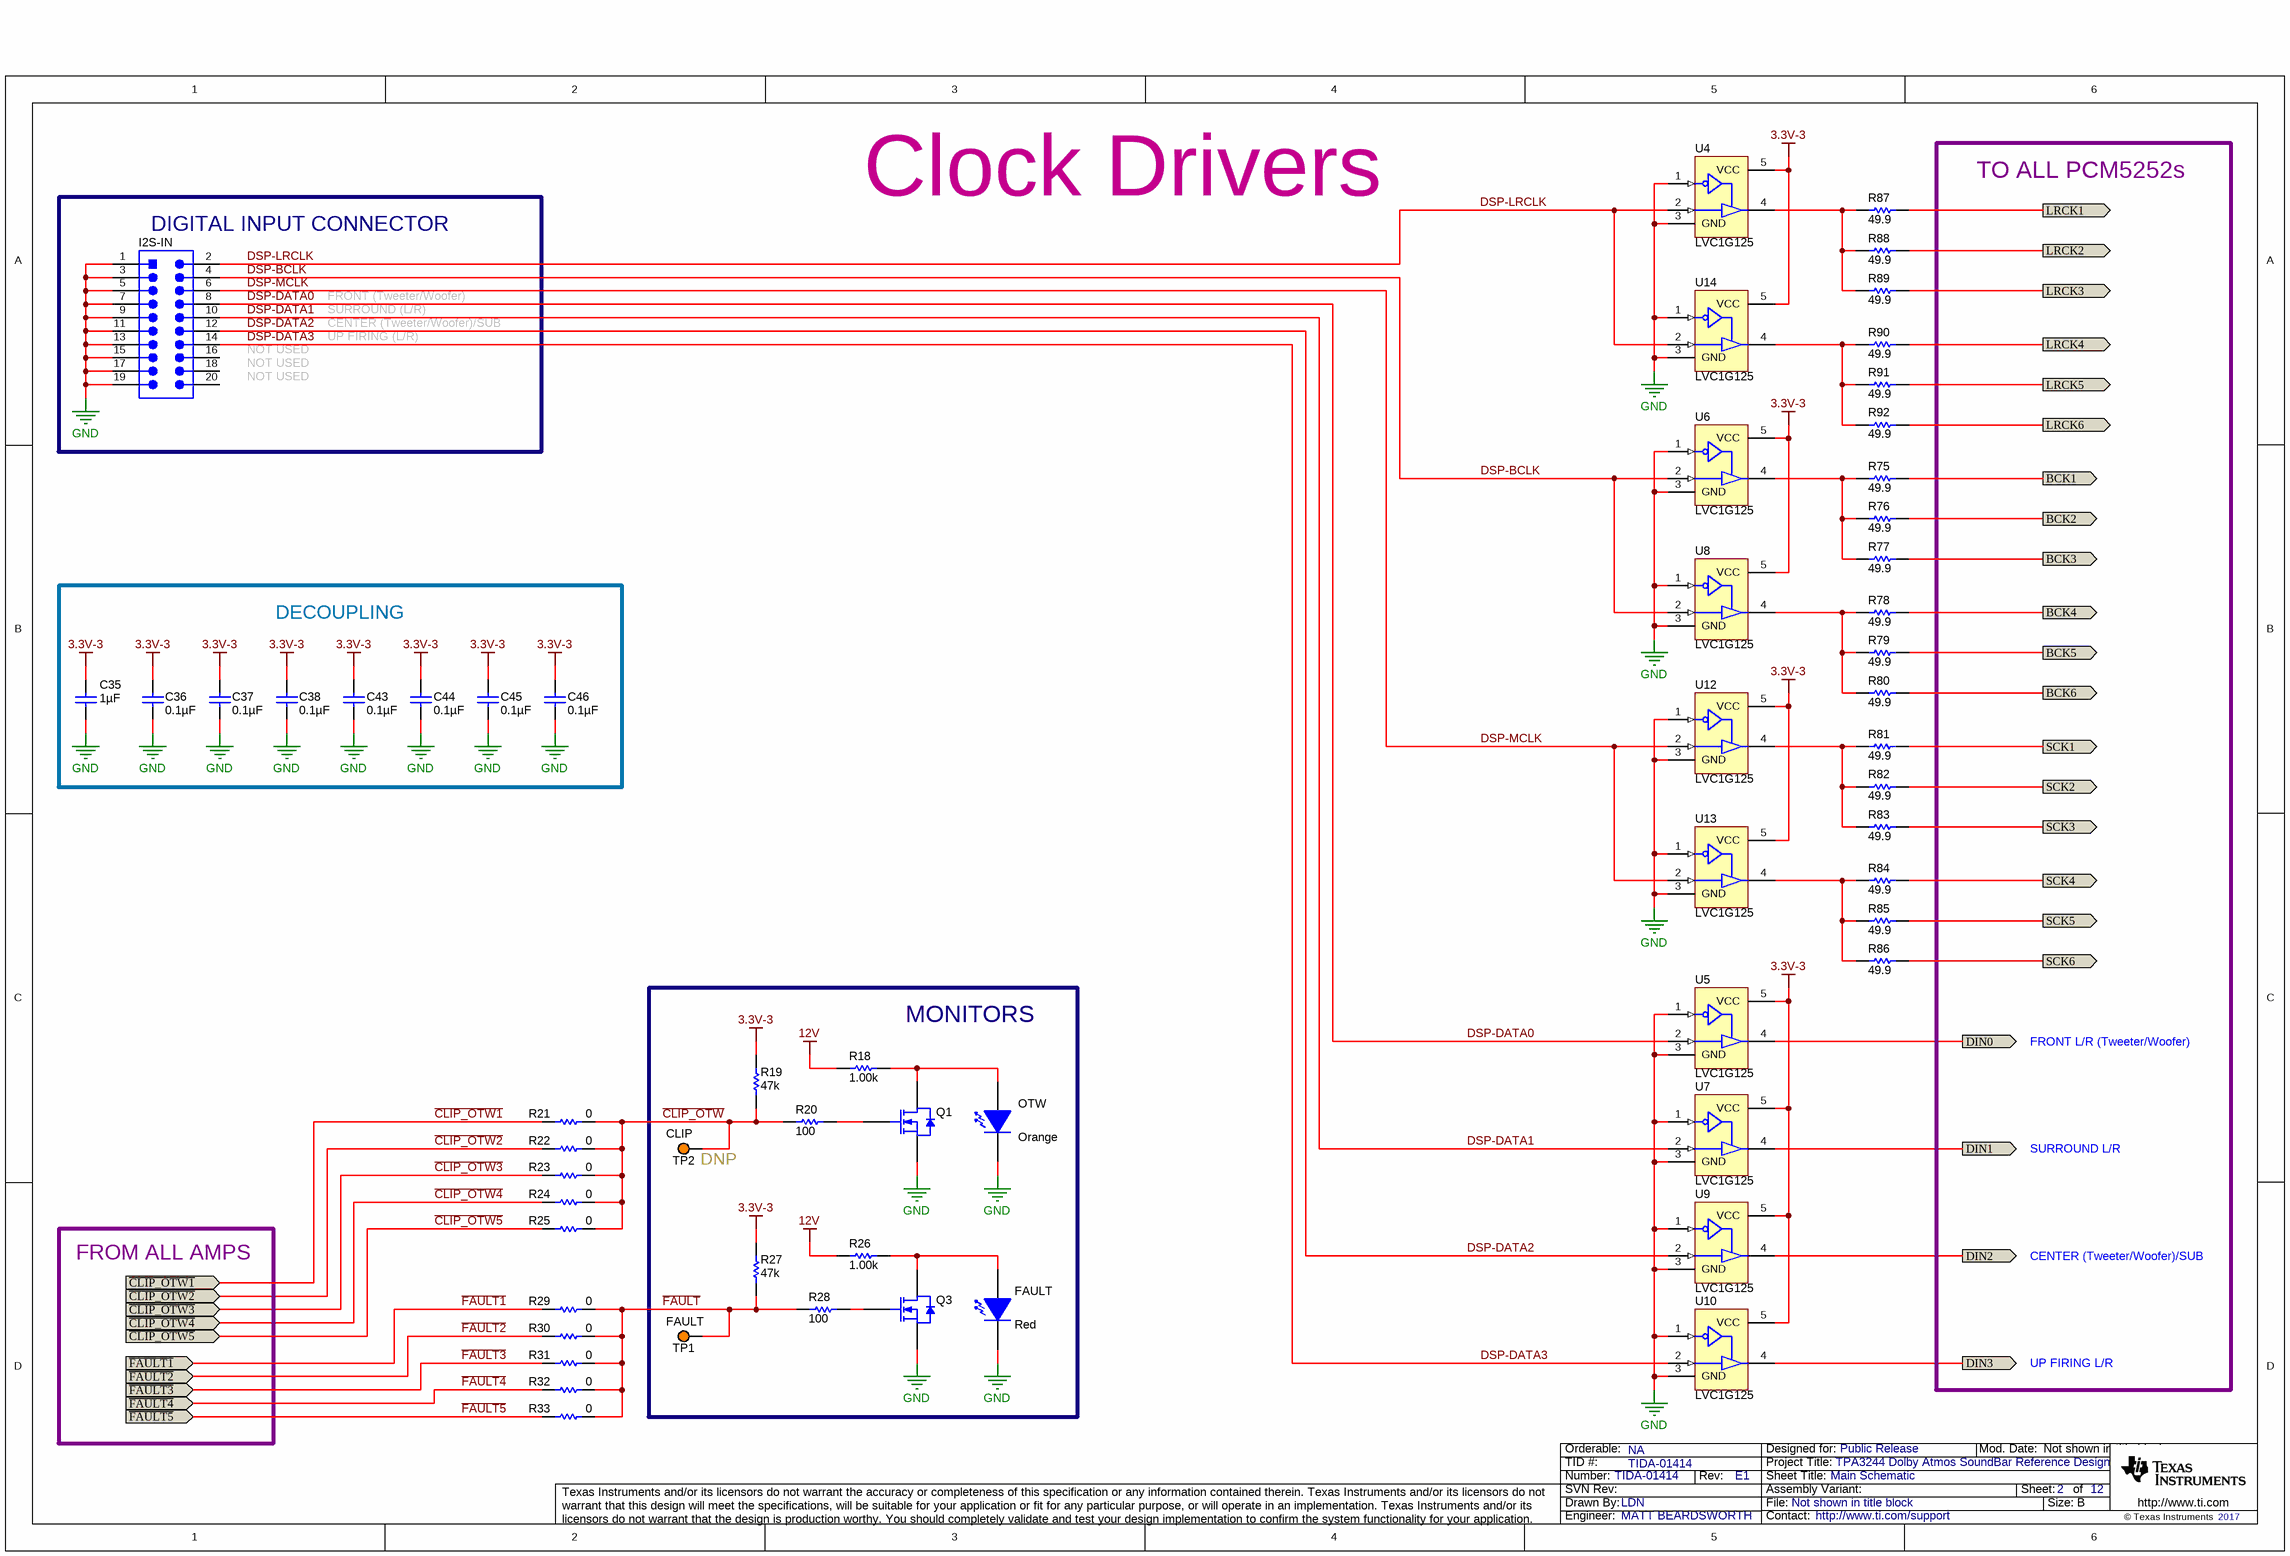
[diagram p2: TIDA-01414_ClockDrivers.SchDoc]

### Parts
C35  ValueDisplayed: 1µF  [0402L]  (hidden comment: C1005X5R0J105M050BB)
C36  ValueDisplayed: 0.1µF  [0402L]  (hidden comment: GRM155R71A104KA01D)
C37  ValueDisplayed: 0.1µF  [0402L]  (hidden comment: GRM155R71A104KA01D)
C38  ValueDisplayed: 0.1µF  [0402L]  (hidden comment: GRM155R71A104KA01D)
C43  ValueDisplayed: 0.1µF  [0402L]  (hidden comment: GRM155R71A104KA01D)
C44  ValueDisplayed: 0.1µF  [0402L]  (hidden comment: GRM155R71A104KA01D)
C45  ValueDisplayed: 0.1µF  [0402L]  (hidden comment: GRM155R71A104KA01D)
C46  ValueDisplayed: 0.1µF  [0402L]  (hidden comment: GRM155R71A104KA01D)
FAULT  value Red  [LED_LTST-C170_Red]
I2S-IN  (no value)  [Sullins_SBH11-xxxC-D10-ST]
OTW  value Orange  [LTST-C170KFKT_Orange]
Q1  2N7002-7-F  [SOT-23]  (value not drawn)
Q3  2N7002-7-F  [SOT-23]  (value not drawn)
R18  ValueDisplayed: 1.00k  [0603L]  (hidden comment: CRCW06031K00FKEA)
R19  ValueDisplayed: 47k  [0603L]  (hidden comment: RC0603JR-0747KL)
R20  ValueDisplayed: 100  [0603L]  (hidden comment: CRCW0603100RFKEA)
R21  ValueDisplayed: 0  [0603L]  (hidden comment: CRCW06030000Z0EA)
R22  ValueDisplayed: 0  [0603L]  (hidden comment: CRCW06030000Z0EA)
R23  ValueDisplayed: 0  [0603L]  (hidden comment: CRCW06030000Z0EA)
R24  ValueDisplayed: 0  [0603L]  (hidden comment: CRCW06030000Z0EA)
R25  ValueDisplayed: 0  [0603L]  (hidden comment: CRCW06030000Z0EA)
R26  ValueDisplayed: 1.00k  [0603L]  (hidden comment: CRCW06031K00FKEA)
R27  ValueDisplayed: 47k  [0603L]  (hidden comment: RC0603JR-0747KL)
R28  ValueDisplayed: 100  [0603L]  (hidden comment: CRCW0603100RFKEA)
R29  ValueDisplayed: 0  [0603L]  (hidden comment: CRCW06030000Z0EA)
R30  ValueDisplayed: 0  [0603L]  (hidden comment: CRCW06030000Z0EA)
R31  ValueDisplayed: 0  [0603L]  (hidden comment: CRCW06030000Z0EA)
R32  ValueDisplayed: 0  [0603L]  (hidden comment: CRCW06030000Z0EA)
R33  ValueDisplayed: 0  [0603L]  (hidden comment: CRCW06030000Z0EA)
R75  ValueDisplayed: 49.9  [0402L]  (hidden comment: CRCW040249R9FKED)
R76  ValueDisplayed: 49.9  [0402L]  (hidden comment: CRCW040249R9FKED)
R77  ValueDisplayed: 49.9  [0402L]  (hidden comment: CRCW040249R9FKED)
R78  ValueDisplayed: 49.9  [0402L]  (hidden comment: CRCW040249R9FKED)
R79  ValueDisplayed: 49.9  [0402L]  (hidden comment: CRCW040249R9FKED)
R80  ValueDisplayed: 49.9  [0402L]  (hidden comment: CRCW040249R9FKED)
R81  ValueDisplayed: 49.9  [0402L]  (hidden comment: CRCW040249R9FKED)
R82  ValueDisplayed: 49.9  [0402L]  (hidden comment: CRCW040249R9FKED)
R83  ValueDisplayed: 49.9  [0402L]  (hidden comment: CRCW040249R9FKED)
R84  ValueDisplayed: 49.9  [0402L]  (hidden comment: CRCW040249R9FKED)
R85  ValueDisplayed: 49.9  [0402L]  (hidden comment: CRCW040249R9FKED)
R86  ValueDisplayed: 49.9  [0402L]  (hidden comment: CRCW040249R9FKED)
R87  ValueDisplayed: 49.9  [0402L]  (hidden comment: CRCW040249R9FKED)
R88  ValueDisplayed: 49.9  [0402L]  (hidden comment: CRCW040249R9FKED)
R89  ValueDisplayed: 49.9  [0402L]  (hidden comment: CRCW040249R9FKED)
R90  ValueDisplayed: 49.9  [0402L]  (hidden comment: CRCW040249R9FKED)
R91  ValueDisplayed: 49.9  [0402L]  (hidden comment: CRCW040249R9FKED)
R92  ValueDisplayed: 49.9  [0402L]  (hidden comment: CRCW040249R9FKED)
TP1  FAULT  [Keystone5003]
TP2  CLIP  [Keystone5003]
U4  LVC1G125  [DCK0005A_N]
U5  LVC1G125  [DCK0005A_N]
U6  LVC1G125  [DCK0005A_N]
U7  LVC1G125  [DCK0005A_N]
U8  LVC1G125  [DCK0005A_N]
U9  LVC1G125  [DCK0005A_N]
U10  LVC1G125  [DCK0005A_N]
U12  LVC1G125  [DCK0005A_N]
U13  LVC1G125  [DCK0005A_N]
U14  LVC1G125  [DCK0005A_N]

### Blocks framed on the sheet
DIGITAL INPUT CONNECTOR: I2S-IN
DECOUPLING: C35-C38 C43-C46
MONITORS: FAULT OTW Q1 Q3 R18-R20 R26-R28 TP1 TP2

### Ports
BCK1 (out), BCK2 (out), BCK3 (out), BCK4 (out), BCK5 (out), BCK6 (out), DIN0 (out), DIN1 (out), DIN2 (out), DIN3 (out), LRCK1 (out), LRCK2 (out), LRCK3 (out), LRCK4 (out), LRCK5 (out), LRCK6 (out), SCK1 (out), SCK2 (out), SCK3 (out), SCK4 (out), SCK5 (out), SCK6 (out), ~{CLIP_OTW1} (in), ~{CLIP_OTW2} (in), ~{CLIP_OTW3} (in), ~{CLIP_OTW4} (in), ~{CLIP_OTW5} (in), ~{FAULT1} (in), ~{FAULT2} (in), ~{FAULT3} (in), ~{FAULT4} (in), ~{FAULT5} (in)

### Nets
3.3V-3: C35.2 C36.2 C37.2 C38.2 C43.2 C44.2 C45.2 C46.2 R19.2 R27.2 U4.5(VCC) U5.5(VCC) U6.5(VCC) U7.5(VCC) U8.5(VCC) U9.5(VCC) U10.5(VCC) U12.5(VCC) U13.5(VCC) U14.5(VCC)
12V: R18.1 R26.1
GND: C35.1 C36.1 C37.1 C38.1 C43.1 C44.1 C45.1 C46.1 FAULT.2(K) I2S-IN.1 I2S-IN.3 I2S-IN.5 I2S-IN.7 I2S-IN.9 I2S-IN.11 I2S-IN.13 I2S-IN.15 I2S-IN.17 I2S-IN.19 OTW.2(K) Q1.2(S) Q3.2(S) U4.1(~{OE}) U4.3(GND) U5.1(~{OE}) U5.3(GND) U6.1(~{OE}) U6.3(GND) U7.1(~{OE}) U7.3(GND) U8.1(~{OE}) U8.3(GND) U9.1(~{OE}) U9.3(GND) U10.1(~{OE}) U10.3(GND) U12.1(~{OE}) U12.3(GND) U13.1(~{OE}) U13.3(GND) U14.1(~{OE}) U14.3(GND)
~{CLIP_OTW}: R19.1 R20.2 R21.1 R22.1 R23.1 R24.1 R25.1 TP2.1
~{CLIP_OTW1}: R21.2 ; port ~{CLIP_OTW1}
~{CLIP_OTW2}: R22.2 ; port ~{CLIP_OTW2}
~{CLIP_OTW3}: R23.2 ; port ~{CLIP_OTW3}
~{CLIP_OTW4}: R24.2 ; port ~{CLIP_OTW4}
~{CLIP_OTW5}: R25.2 ; port ~{CLIP_OTW5}
~{FAULT}: R27.1 R28.2 R29.1 R30.1 R31.1 R32.1 R33.1 TP1.1
~{FAULT1}: R29.2 ; port ~{FAULT1}
~{FAULT2}: R30.2 ; port ~{FAULT2}
~{FAULT3}: R31.2 ; port ~{FAULT3}
~{FAULT4}: R32.2 ; port ~{FAULT4}
~{FAULT5}: R33.2 ; port ~{FAULT5}
BCK1: R75.1 ; port BCK1
BCK2: R76.1 ; port BCK2
BCK3: R77.1 ; port BCK3
BCK4: R78.1 ; port BCK4
BCK5: R79.1 ; port BCK5
BCK6: R80.1 ; port BCK6
DIN0: U5.4(Y) ; port DIN0
DIN1: U7.4(Y) ; port DIN1
DIN2: U9.4(Y) ; port DIN2
DIN3: U10.4(Y) ; port DIN3
DSP-BCLK: I2S-IN.4 U6.2(A) U8.2(A)
DSP-DATA0: I2S-IN.8 U5.2(A)
DSP-DATA1: I2S-IN.10 U7.2(A)
DSP-DATA2: I2S-IN.12 U9.2(A)
DSP-DATA3: I2S-IN.14 U10.2(A)
DSP-LRCLK: I2S-IN.2 U4.2(A) U14.2(A)
DSP-MCLK: I2S-IN.6 U12.2(A) U13.2(A)
LRCK1: R87.1 ; port LRCK1
LRCK2: R88.1 ; port LRCK2
LRCK3: R89.1 ; port LRCK3
LRCK4: R90.1 ; port LRCK4
LRCK5: R91.1 ; port LRCK5
LRCK6: R92.1 ; port LRCK6
SCK1: R81.1 ; port SCK1
SCK2: R82.1 ; port SCK2
SCK3: R83.1 ; port SCK3
SCK4: R84.1 ; port SCK4
SCK5: R85.1 ; port SCK5
SCK6: R86.1 ; port SCK6
NetFAULT_1: FAULT.1(A) Q3.3(D) R26.2
NetOTW_1: OTW.1(A) Q1.3(D) R18.2
NetQ1_1: Q1.1(G) R20.1
NetQ3_1: Q3.1(G) R28.1
NetR75_2: R75.2 R76.2 R77.2 U6.4(Y)
NetR78_2: R78.2 R79.2 R80.2 U8.4(Y)
NetR81_2: R81.2 R82.2 R83.2 U12.4(Y)
NetR84_2: R84.2 R85.2 R86.2 U13.4(Y)
NetR87_2: R87.2 R88.2 R89.2 U4.4(Y)
NetR90_2: R90.2 R91.2 R92.2 U14.4(Y)

Not connected (* = marked no-connect by the designer): I2S-IN 16 18 20

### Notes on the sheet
- Clock Drivers
- TO ALL PCM5252s
- FRONT (Tweeter/Woofer)
- NOT USED
- SURROUND (L/R)
- CENTER (Tweeter/Woofer)/SUB
- UP FIRING (L/R)
- FRONT L/R (Tweeter/Woofer)
- (near TP2) DNP
- SURROUND L/R
- FROM ALL AMPS
- UP FIRING L/R

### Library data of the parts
C35 = C1005X5R0J105M050BB: as C55 on sheet TIDA-01414_Control
C36-C38 C43-C46 = GRM155R71A104KA01D: as C29 on sheet TIDA-01414_Control
FAULT = LTST-C170KRKT: LED, Red, SMD; Manufacturer: Lite-On; Vf_V: 2; Value2: 2V; Io_A: 0.02; Value1: W; SizeAreaWB_mm2: 6.75; SizeArea_mm2: 2.5; SizeY_mm: 1.25; SizeZ_mm: 1.2; U/M: EA
I2S-IN = SBH11-PBPC-D10-ST-BK: Header (Shrouded), 2.54mm, 10x2, Gold, Black, TH; Manufacturer: Sullins Connector Solutions; SymbolCreator: a0412235; Pitch_mm: 2.54; Gender: Male; Shrouded: Y; Row_Count: 2; Current_A: 3; Voltage_V: 1000
OTW = LTST-C170KFKT: LED, Orange, SMD; Manufacturer: Lite-On; Vf_V: 2; Value2: 2V; Io_A: 0.02; Value1: W; U/M: EA
Q1 Q3 = 2N7002-7-F: MOSFET, N-CH, 60 V, 0.17 A, SOT-23; Manufacturer: Diodes Inc.; Alternate Manufacturer: None; U/M: EA; ChType: N; Value: 60V; VdsMax_V: 60; Value1: 7.5 ohm; Rdson45_ohm: 7.5; Value2: 223 nC; QgTyp_nC: 223; Vgs_V: 20; IdsMax_A: 0.17; AEC Category: Q101
R18 R26 = CRCW06031K00FKEA: RES, 1.00 k, 1%, 0.1 W, 0603; Manufacturer: Vishay-Dale; CompType: Resistor; Value: 1.00k; Res_ohm: 1000; Value_Code: 1k00; Tolerance_%: 1; Power_W: 0.1; Value2: 0.1W; VDC_V: 75; TempCo: 100 ppm/C; EIA_Code: E96; U/M: EA; AEC Category: Q200
R19 R27 = RC0603JR-0747KL: RES, 47 k, 5%, 0.1 W, 0603; Manufacturer: Yageo America; CompType: Resistor; Value: 47k; Res_ohm: 47000; Value_Code: 47k0; Tolerance_%: 5; Power_W: 0.1; Value2: 0.1W; VDC_V: 50; TempCo: 100 ppm/C; EIA_Code: E24; U/M: EA; AEC Category: Q200
R20 R28 = CRCW0603100RFKEA: RES, 100, 1%, 0.1 W, 0603; Manufacturer: Vishay-Dale; CompType: Resistor; Value: 100; Value_Code: 100R; Tolerance_%: 1; Power_W: 0.1; Value2: 0.1W; VDC_V: 75; TempCo: 100 ppm/C; EIA_Code: E96; U/M: EA; AEC Category: Q200
R21-R25 R29-R33 = CRCW06030000Z0EA: as R2 on sheet TIDA-01414_Control
R75-R92 = CRCW040249R9FKED: RES, 49.9, 1%, 0.063 W, 0402; Manufacturer: Vishay-Dale; CompType: Resistor; Value: 49.9; Value_Code: 49R9; Tolerance_%: 1; Power_W: 0.063; Value2: 0.063W; VDC_V: 50; TempCo: 100 ppm/C; EIA_Code: E96; U/M: EA; AEC Category: Q200; SizeArea_mm2: 0.5; SizeZ_mm: 0.6
TP1 TP2 = 5003: Test Point, Miniature, Orange, TH; Manufacturer: Keystone; CompType: Test Point Loop; ContactFinish: Silver
U4-U10 U12-U14 = SN74LVC1G125DCKR: Single Bus Buffer Gate With 3-State Output, DCK0005A; Alternate PartNumber: SN74LVC1G125DCKT; Manufacturer: Texas Instruments; SymbolCreator: Altium; CompType: IC; U/M: EA

## Sheet TIDA-01414_SurroundChannel.SchDoc: Main Schematic
size 538 x 342 mm; Date: Not shown in title block; ApprovedBy: Not shown in title block; CheckedBy: Not shown in title block; Author: Not shown in title block; CompanyName: Not shown in title block; DrawnBy: LDN; Engineer: Not shown in title block; Organization: Not shown in title block; Address1: Not shown in title block; Address2: Not shown in title block; Address3: Not shown in title block; Address4: Not shown in title block; DocumentNumber: 3; Revision: Use project parameter SCH_Rev; SheetNumber: 3; SheetTotal: 12; PageSetup: Record=PageOptions¦CenterHorizontal=True¦CenterVertical=True¦PrintScale=1.00¦XCorrection=1.00¦YCorrection=1.00¦PrintKind=0¦BorderSize=5000000¦LeftOffset=0¦BottomOffset=0¦Orientation=2¦PaperLength=1000¦PaperWidth=1000¦Scale=100¦PaperSource=15¦PrintQuality=600¦MediaType=1¦DitherType=10¦PaperKind=Letter¦PrintScaleMode=1
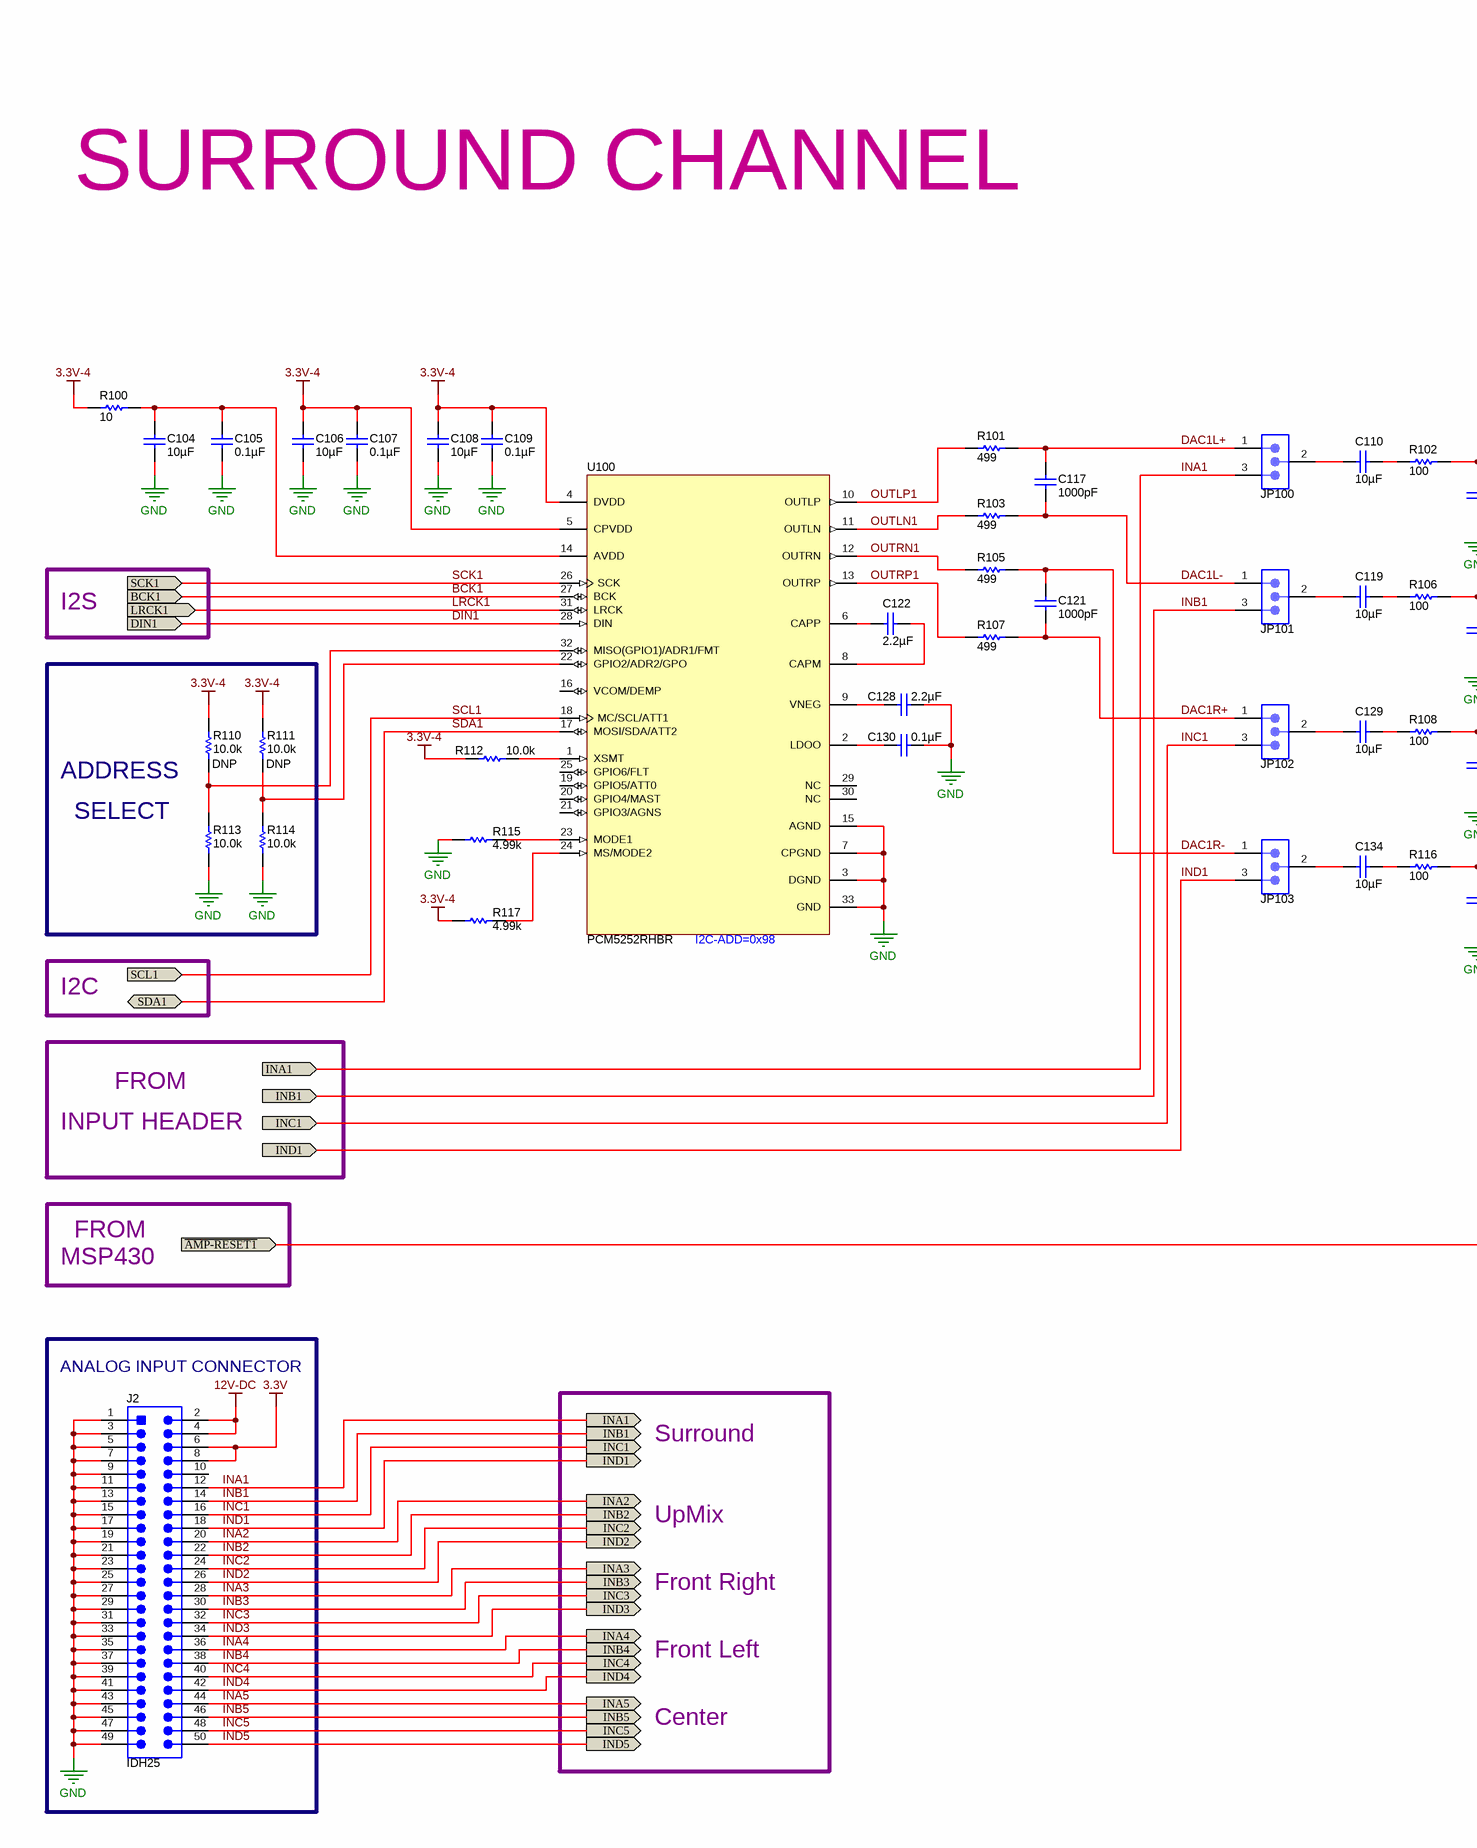
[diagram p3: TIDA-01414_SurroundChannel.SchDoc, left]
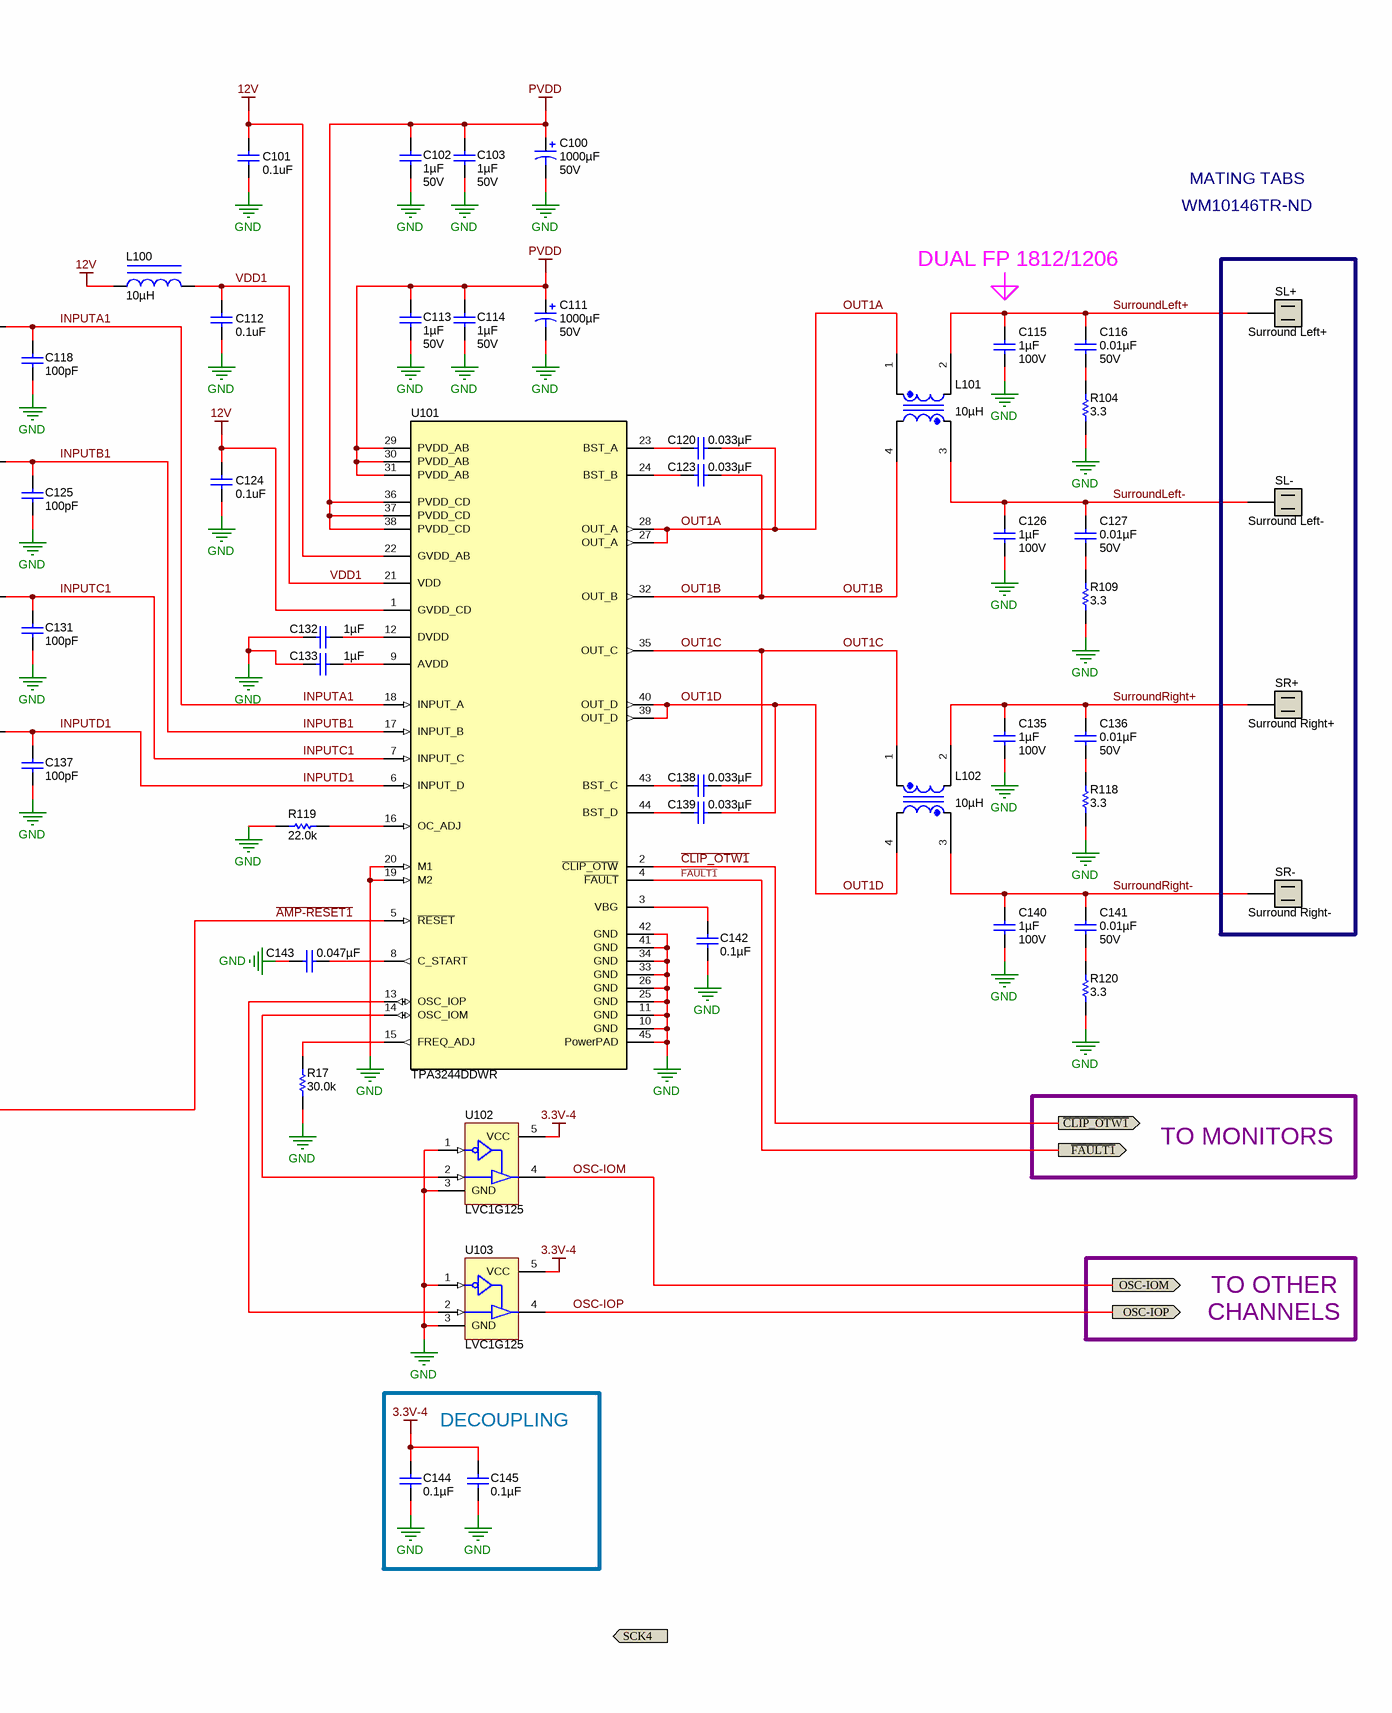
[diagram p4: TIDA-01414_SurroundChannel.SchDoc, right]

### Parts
C100  ValueDisplayed: 1000µF  Value2: 50V  [SM_RADIAL_J16]  (hidden comment: +)
C101  value 0.1uF  [0603L]  (hidden comment: C0603C104K5RACTU)
C102  ValueDisplayed: 1µF  Value2: 50V  [1206L]  (hidden comment: GRM31MR71H105KA88L)
C103  ValueDisplayed: 1µF  Value2: 50V  [1206L]  (hidden comment: GRM31MR71H105KA88L)
C104  ValueDisplayed: 10µF  [0603L]  (hidden comment: GRM188R61A106ME69D)
C105  ValueDisplayed: 0.1µF  [0402L]  (hidden comment: GRM155R71A104KA01D)
C106  ValueDisplayed: 10µF  [0603L]  (hidden comment: GRM188R61A106ME69D)
C107  ValueDisplayed: 0.1µF  [0402L]  (hidden comment: GRM155R71A104KA01D)
C108  ValueDisplayed: 10µF  [0603L]  (hidden comment: GRM188R61A106ME69D)
C109  ValueDisplayed: 0.1µF  [0402L]  (hidden comment: GRM155R71A104KA01D)
C110  ValueDisplayed: 10µF  [1206_180]  (hidden comment: GRM31CR71C106KAC7L)
C111  ValueDisplayed: 1000µF  Value2: 50V  [SM_RADIAL_J16]  (hidden comment: +)
C112  value 0.1uF  [0603L]  (hidden comment: C0603C104K5RACTU)
C113  ValueDisplayed: 1µF  Value2: 50V  [1206L]  (hidden comment: GRM31MR71H105KA88L)
C114  ValueDisplayed: 1µF  Value2: 50V  [1206L]  (hidden comment: GRM31MR71H105KA88L)
C115  ValueDisplayed: 1µF  Value2: 100V  [1210_220]  (hidden comment: C3225X7R2A105K200AA)
C116  ValueDisplayed: 0.01µF  Value2: 50V  [0603L]  (hidden comment: C0603C103K5RACTU)
C117  ValueDisplayed: 1000pF  [0402L]  (hidden comment: GRM1555C1H102JA01D)
C118  ValueDisplayed: 100pF  [0603L]  (hidden comment: GRM1885C1H101JA01D)
C119  ValueDisplayed: 10µF  [1206_180]  (hidden comment: GRM31CR71C106KAC7L)
C120  ValueDisplayed: 0.033µF  [0603L]  (hidden comment: GRM188R71E333KA01D)
C121  ValueDisplayed: 1000pF  [0402L]  (hidden comment: GRM1555C1H102JA01D)
C122  ValueDisplayed: 2.2µF  [0402L]  (hidden comment: C1005X5R1A225K050BC)
C123  ValueDisplayed: 0.033µF  [0603L]  (hidden comment: GRM188R71E333KA01D)
C124  value 0.1uF  [0603L]  (hidden comment: C0603C104K5RACTU)
C125  ValueDisplayed: 100pF  [0603L]  (hidden comment: GRM1885C1H101JA01D)
C126  ValueDisplayed: 1µF  Value2: 100V  [1210_220]  (hidden comment: C3225X7R2A105K200AA)
C127  ValueDisplayed: 0.01µF  Value2: 50V  [0603L]  (hidden comment: C0603C103K5RACTU)
C128  ValueDisplayed: 2.2µF  [0402L]  (hidden comment: C1005X5R1A225K050BC)
C129  ValueDisplayed: 10µF  [1206_180]  (hidden comment: GRM31CR71C106KAC7L)
C130  ValueDisplayed: 0.1µF  [0402L]  (hidden comment: GRM155R71A104KA01D)
C131  ValueDisplayed: 100pF  [0603L]  (hidden comment: GRM1885C1H101JA01D)
C132  ValueDisplayed: 1µF  [0603L]  (hidden comment: GRM188R71C105KA12D)
C133  ValueDisplayed: 1µF  [0603L]  (hidden comment: GRM188R71C105KA12D)
C134  ValueDisplayed: 10µF  [1206_180]  (hidden comment: GRM31CR71C106KAC7L)
C135  ValueDisplayed: 1µF  Value2: 100V  [1210_220]  (hidden comment: C3225X7R2A105K200AA)
C136  ValueDisplayed: 0.01µF  Value2: 50V  [0603L]  (hidden comment: C0603C103K5RACTU)
C137  ValueDisplayed: 100pF  [0603L]  (hidden comment: GRM1885C1H101JA01D)
C138  ValueDisplayed: 0.033µF  [0603L]  (hidden comment: GRM188R71E333KA01D)
C139  ValueDisplayed: 0.033µF  [0603L]  (hidden comment: GRM188R71E333KA01D)
C140  ValueDisplayed: 1µF  Value2: 100V  [1210_220]  (hidden comment: C3225X7R2A105K200AA)
C141  ValueDisplayed: 0.01µF  Value2: 50V  [0603L]  (hidden comment: C0603C103K5RACTU)
C142  ValueDisplayed: 0.1µF  [0603L]  (hidden comment: C0603C104K5RACTU)
C143  ValueDisplayed: 0.047µF  [0603L]  (hidden comment: GRM188R71H473KA61D)
C144  ValueDisplayed: 0.1µF  [0402L]  (hidden comment: GRM155R71A104KA01D)
C145  ValueDisplayed: 0.1µF  [0402L]  (hidden comment: GRM155R71A104KA01D)
J2  IDH25  [3M_N2550-6002-RB]
JP100  PBC03SAAN  [PBC03SAAN]  (value not drawn)
JP101  PBC03SAAN  [PBC03SAAN]  (value not drawn)
JP102  PBC03SAAN  [PBC03SAAN]  (value not drawn)
JP103  PBC03SAAN  [PBC03SAAN]  (value not drawn)
L100  ValueDisplayed: 10µH  [0603L]  (hidden comment: GLFR1608T100M-LR)
L101  ValueDisplayed: 10µH  [Coilcraft_RA7231-ALB]  (hidden comment: UA8014-ALD)
L102  ValueDisplayed: 10µH  [Coilcraft_RA7231-ALB]  (hidden comment: UA8014-ALD)
R17  ValueDisplayed: 30.0k  [0603L]  (hidden comment: RC0603FR-0730KL)
R100  ValueDisplayed: 10  [0603L]  (hidden comment: CRCW060310R0JNEA)
R101  ValueDisplayed: 499  [0603L]  (hidden comment: CRCW0603499RFKEA)
R102  ValueDisplayed: 100  [0603L]  (hidden comment: CRCW0603100RFKEA)
R103  ValueDisplayed: 499  [0603L]  (hidden comment: CRCW0603499RFKEA)
R104  ValueDisplayed: 3.3  [0603L]  (hidden comment: CRCW06033R30JNEA)
R105  ValueDisplayed: 499  [0603L]  (hidden comment: CRCW0603499RFKEA)
R106  ValueDisplayed: 100  [0603L]  (hidden comment: CRCW0603100RFKEA)
R107  ValueDisplayed: 499  [0603L]  (hidden comment: CRCW0603499RFKEA)
R108  ValueDisplayed: 100  [0603L]  (hidden comment: CRCW0603100RFKEA)
R109  ValueDisplayed: 3.3  [0603L]  (hidden comment: CRCW06033R30JNEA)
R110  DNP  ValueDisplayed: 10.0k  [0402L]
R111  DNP  ValueDisplayed: 10.0k  [0402L]
R112  ValueDisplayed: 10.0k  [0402L]  (hidden comment: ERJ-2RKF1002X)
R113  ValueDisplayed: 10.0k  [0402L]  (hidden comment: ERJ-2RKF1002X)
R114  ValueDisplayed: 10.0k  [0402L]  (hidden comment: ERJ-2RKF1002X)
R115  ValueDisplayed: 4.99k  [0402L]  (hidden comment: CRCW04024K99FKED)
R116  ValueDisplayed: 100  [0603L]  (hidden comment: CRCW0603100RFKEA)
R117  ValueDisplayed: 4.99k  [0402L]  (hidden comment: CRCW04024K99FKED)
R118  ValueDisplayed: 3.3  [0603L]  (hidden comment: CRCW06033R30JNEA)
R119  ValueDisplayed: 22.0k  [0603L]  (hidden comment: RC0603FR-0722KL)
R120  ValueDisplayed: 3.3  [0603L]  (hidden comment: CRCW06033R30JNEA)
SL+  Surround Left+  [TEC-SpadeLug_63066-1]
SL-  Surround Left-  [TEC-SpadeLug_63066-1]
SR+  Surround Right+  [TEC-SpadeLug_63066-1]
SR-  Surround Right-  [TEC-SpadeLug_63066-1]
U100  PCM5252RHBR  [RHB0032E]
U101  TPA3244DDWR  [DDW0044D_N]
U102  LVC1G125  [DCK0005A_N]
U103  LVC1G125  [DCK0005A_N]

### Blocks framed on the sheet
ANALOG INPUT CONNECTOR: J2
DECOUPLING: C144 C145

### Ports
BCK1 (in), DIN1 (in), INA1 (in), INA1 (out), INA2 (out), INA3 (out), INA4 (out), INA5 (out), INB1 (in), INB1 (out), INB2 (out), INB3 (out), INB4 (out), INB5 (out), INC1 (in), INC1 (out), INC2 (out), INC3 (out), INC4 (out), INC5 (out), IND1 (in), IND1 (out), IND2 (out), IND3 (out), IND4 (out), IND5 (out), LRCK1 (in), OSC-IOM (out), OSC-IOP (out), SCK1 (in), SCK4 (out), SCL1 (in), SDA1 (bidir), ~{AMP-RESET1} (in), ~{CLIP_OTW1} (out), ~{FAULT1} (out)

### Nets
3.3V: J2.6 J2.8
3.3V-4: C106.1 C107.1 C108.1 C109.1 C144.2 C145.2 R100.1 R110.2 R111.2 R112.1 R117.2 U100.4(DVDD) U100.5(CPVDD) U102.5(VCC) U103.5(VCC)
12V: C101.1 C124.1 L100.1 U101.1(GVDD_CD) U101.22(GVDD_AB)
12V-DC: J2.2 J2.4
GND: C100.2(-) C101.2 C102.1 C103.1 C104.2 C105.2 C106.2 C107.2 C108.2 C109.2 C111.2(-) C112.2 C113.1 C114.1 C115.2 C118.2 C124.2 C125.2 C126.2 C128.2 C130.2 C131.2 C132.1 C133.1 C135.2 C137.2 C140.2 C142.1 C143.2 C144.1 C145.1 J2.1 J2.3 J2.5 J2.7 J2.9 J2.11 J2.13 J2.15 J2.17 J2.19 J2.21 J2.23 J2.25 J2.27 J2.29 J2.31 J2.33 J2.35 J2.37 J2.39 J2.41 J2.43 J2.45 J2.47 J2.49 R17.1 R104.1 R109.1 R113.1 R114.1 R115.2 R118.1 R119.1 R120.1 U100.3(DGND) U100.7(CPGND) U100.15(AGND) U100.33(GND) U101.10(GND) U101.11(GND) U101.19(M2) U101.20(M1) U101.25(GND) U101.26(GND) U101.33(GND) U101.34(GND) U101.41(GND) U101.42(GND) U101.45(PowerPAD) U102.1(~{OE}) U102.3(GND) U103.1(~{OE}) U103.3(GND)
PVDD: C100.1(+) C102.2 C103.2 C111.1(+) C113.2 C114.2 U101.29(PVDD_AB) U101.30(PVDD_AB) U101.31(PVDD_AB) U101.36(PVDD_CD) U101.37(PVDD_CD) U101.38(PVDD_CD)
~{AMP-RESET1}: U101.5(~{RESET}) ; port ~{AMP-RESET1}
~{CLIP_OTW1}: U101.2(~{CLIP_OTW}) ; port ~{CLIP_OTW1}
~{FAULT1}: U101.4(~{FAULT}) ; port ~{FAULT1}
BCK1: U100.27(BCK) ; port BCK1
DAC1L+: C117.1 JP100.1 R101.2
DAC1L-: C117.2 JP101.1 R103.2
DAC1R+: C121.2 JP102.1 R107.2
DAC1R-: C121.1 JP103.1 R105.2
DIN1: U100.28(DIN) ; port DIN1
INA1: J2.12 JP100.3 ; port INA1
INA2: J2.20 ; port INA2
INA3: J2.28 ; port INA3
INA4: J2.36 ; port INA4
INA5: J2.44 ; port INA5
INB1: J2.14 JP101.3 ; port INB1
INB2: J2.22 ; port INB2
INB3: J2.30 ; port INB3
INB4: J2.38 ; port INB4
INB5: J2.46 ; port INB5
INC1: J2.16 JP102.3 ; port INC1
INC2: J2.24 ; port INC2
INC3: J2.32 ; port INC3
INC4: J2.40 ; port INC4
INC5: J2.48 ; port INC5
IND1: J2.18 JP103.3 ; port IND1
IND2: J2.26 ; port IND2
IND3: J2.34 ; port IND3
IND4: J2.42 ; port IND4
IND5: J2.50 ; port IND5
INPUTA1: C118.1 R102.2 U101.18(INPUT_A)
INPUTB1: C125.1 R106.2 U101.17(INPUT_B)
INPUTC1: C131.1 R108.2 U101.7(INPUT_C)
INPUTD1: C137.1 R116.2 U101.6(INPUT_D)
LRCK1: U100.31(LRCK) ; port LRCK1
OSC-IOM: U102.4(Y) ; port OSC-IOM
OSC-IOP: U103.4(Y) ; port OSC-IOP
OUT1A: C120.1 L101.1 U101.27(OUT_A) U101.28(OUT_A)
OUT1B: C123.1 L101.4 U101.32(OUT_B)
OUT1C: C138.1 L102.1 U101.35(OUT_C)
OUT1D: C139.1 L102.4 U101.39(OUT_D) U101.40(OUT_D)
OUTLN1: R103.1 U100.11(OUTLN)
OUTLP1: R101.1 U100.10(OUTLP)
OUTRN1: R105.1 U100.12(OUTRN)
OUTRP1: R107.1 U100.13(OUTRP)
SCK1: U100.26(SCK) ; port SCK1
SCL1: U100.18(MC/SCL/ATT1) ; port SCL1
SDA1: U100.17(MOSI/SDA/ATT2) ; port SDA1
SurroundLeft+: C115.1 C116.1 L101.2 SL+.1
SurroundLeft-: C126.1 C127.1 L101.3 SL-.1
SurroundRight+: C135.1 C136.1 L102.2 SR+.1
SurroundRight-: C140.1 C141.1 L102.3 SR-.1
VDD1: C112.1 L100.2 U101.21(VDD)
NetC104_1: C104.1 C105.1 R100.2 U100.14(AVDD)
NetC110_1: C110.1 JP100.2
NetC110_2: C110.2 R102.1
NetC116_2: C116.2 R104.2
NetC119_1: C119.1 JP101.2
NetC119_2: C119.2 R106.1
NetC120_2: C120.2 U101.23(BST_A)
NetC122_1: C122.1 U100.6(CAPP)
NetC122_2: C122.2 U100.8(CAPM)
NetC123_2: C123.2 U101.24(BST_B)
NetC127_2: C127.2 R109.2
NetC128_1: C128.1 U100.9(VNEG)
NetC129_1: C129.1 JP102.2
NetC129_2: C129.2 R108.1
NetC130_1: C130.1 U100.2(LDOO)
NetC132_2: C132.2 U101.12(DVDD)
NetC133_2: C133.2 U101.9(AVDD)
NetC134_1: C134.1 JP103.2
NetC134_2: C134.2 R116.1
NetC136_2: C136.2 R118.2
NetC138_2: C138.2 U101.43(BST_C)
NetC139_2: C139.2 U101.44(BST_D)
NetC141_2: C141.2 R120.2
NetC142_2: C142.2 U101.3(VBG)
NetC143_1: C143.1 U101.8(C_START)
NetR17_2: R17.2 U101.15(FREQ_ADJ)
NetR110_1: R110.1 R113.2 U100.32(MISO(GPIO1)/ADR1/FMT)
NetR111_1: R111.1 R114.2 U100.22(GPIO2/ADR2/GPO)
NetR112_2: R112.2 U100.1(XSMT)
NetR115_1: R115.1 U100.23(MODE1)
NetR117_1: R117.1 U100.24(MS/MODE2)
NetR119_2: R119.2 U101.16(OC_ADJ)
NetU101_13: U101.13(OSC_IOP) U103.2(A)
NetU101_14: U101.14(OSC_IOM) U102.2(A)

Not connected (* = marked no-connect by the designer): J2 10; U100 16(VCOM/DEMP) 19(GPIO5/ATT0) 20(GPIO4/MAST) 21(GPIO3/AGNS) 25(GPIO6/FLT) 29(NC) 30(NC)

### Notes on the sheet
- SURROUND CHANNEL
- MATING TABS
- WM10146TR-ND
- DUAL FP 1812/1206
- I2S
- ADDRESS
- SELECT
- (near U100) I2C-ADD=0x98
- I2C
- FROM
- INPUT HEADER
- MSP430
- TO MONITORS
- Surround
- TO OTHER
- CHANNELS
- UpMix
- Front Right
- Front Left
- Center

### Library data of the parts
C100 C111 = EEV-FK1H102M: CAP, AL, 1000 µF, 50 V, +/- 20%, 0.073 ohm, AEC-Q200 Grade 2, SMD; Manufacturer: Panasonic; Polarized: Y; CompType: Capacitor; Value: 1000uF; U/M: EA; Cap_F: 0.001; Tolerance_%: 20; VDC_V: 50; ESR_ohm: 0.073; IRMS_A: 1.61; TaMin_C: -55; TaMax_C: 105; Cap_Case: J16; SizeAreaWB_mm2: 399; SizeArea_mm2: 323; SizeX_mm: 19; SizeY_mm: 17; SizeZ_mm: 16.5; AEC Category: Q200; AEC Grade: 2
C101 C112 C124 = C0603C104K5RACTU: CAP, CERM, 0.1 µF, 50 V, +/- 10%, X7R, 0603; Manufacturer: Kemet; Polarized: N; CompType: Capacitor; ValueDisplayed: 0.1µF; U/M: EA; Cap_F: 0.0000001; Tolerance_%: 10; Value1: Unknown; VDC_V: 50; Value2: 50V; TaMin_C: -55; TaMax_C: 125; Cap_Case: 0603; AEC Category: Q200
C102 C103 C113 C114 = GRM31MR71H105KA88L: CAP, CERM, 1 µF, 50 V, +/- 10%, X7R, 1206; Manufacturer: MuRata; Polarized: N; CompType: Capacitor; Value: 1uF; U/M: EA; Cap_F: 0.000001; Tolerance_%: 10; Value1: Unknown; VDC_V: 50; TaMin_C: -55; TaMax_C: 125; Cap_Case: 1206; AEC Category: Q200
C104 C106 C108 = GRM188R61A106ME69D: CAP, CERM, 10 µF, 10 V, +/- 20%, X5R, 0603; Manufacturer: MuRata; Polarized: N; CompType: Capacitor; Value: 10uF; U/M: EA; Cap_F: 0.00001; Tolerance_%: 20; Value1: Unknown; VDC_V: 10; Value2: 10V; TaMin_C: -55; TaMax_C: 85; Cap_Case: 0603; AEC Category: Q200
C105 C107 C109 C130 C144 C145 = GRM155R71A104KA01D: as C29 on sheet TIDA-01414_Control
C110 C119 C129 C134 = GRM31CR71C106KAC7L: CAP, CERM, 10 µF, 16 V, +/- 10%, X7R, 1206; Manufacturer: MuRata; Polarized: N; CompType: Capacitor; Value: 10uF; U/M: EA; Cap_F: 0.00001; Tolerance_%: 10; Value1: Unknown; VDC_V: 16; Value2: 16V; TaMin_C: -55; TaMax_C: 125; Cap_Case: 1206; AEC Category: Q200; SizeArea_mm2: 5.12; SizeAreaWB_mm2: 10.92; SizeX_mm: 3.2; SizeY_mm: 1.6; SizeZ_mm: 1.8
C115 C126 C135 C140 = C3225X7R2A105K200AA: CAP, CERM, 1 µF, 100 V, +/- 10%, X7R, 1210; Manufacturer: TDK; Polarized: N; CompType: Capacitor; Value: 1uF; U/M: EA; Cap_F: 0.000001; Tolerance_%: 10; Value1: 0.004956 ohm; VDC_V: 100; ESR_ohm: 0.004956; IRMS_A: 3.30731; TaMin_C: -55; TaMax_C: 125; AEC Category: Q200; SizeArea_mm2: 8; SizeAreaWB_mm2: 14.7; SizeX_mm: 3.2; SizeY_mm: 2.5; SizeZ_mm: 2.2
C116 C127 C136 C141 = C0603C103K5RACTU: CAP, CERM, 0.01 µF, 50 V, +/- 10%, X7R, 0603; Manufacturer: Kemet; Polarized: N; CompType: Capacitor; Value: 0.01uF; U/M: EA; Cap_F: 0.00000001; Tolerance_%: 10; Value1: Unknown; VDC_V: 50; TaMin_C: -55; TaMax_C: 125; Cap_Case: 0603; AEC Category: Q200
C117 C121 = GRM1555C1H102JA01D: CAP, CERM, 1000 pF, 50 V, +/- 5%, C0G/NP0, 0402; Manufacturer: MuRata; Polarized: N; CompType: Capacitor; Value: 1000pF; U/M: EA; Cap_F: 0.000000001; Tolerance_%: 5; Value1: Unknown; VDC_V: 50; Value2: 50V; TaMin_C: -55; TaMax_C: 125; Cap_Case: 0402; AEC Category: Q200
C118 C125 C131 C137 = GRM1885C1H101JA01D: CAP, CERM, 100 pF, 50 V, +/- 5%, C0G/NP0, 0603; Manufacturer: MuRata; Polarized: N; CompType: Capacitor; Value: 100pF; U/M: EA; Cap_F: 0.0000000001; Tolerance_%: 5; Value1: Unknown; VDC_V: 50; Value2: 50V; TaMin_C: -55; TaMax_C: 125; Cap_Case: 0603; AEC Category: Q200
C120 C123 C138 C139 = GRM188R71E333KA01D: CAP, CERM, 0.033 µF, 25 V, +/- 10%, X7R, 0603; Manufacturer: MuRata; Polarized: N; CompType: Capacitor; Value: 0.033uF; U/M: EA; Cap_F: 0.000000033; Tolerance_%: 10; Value1: Unknown; VDC_V: 25; Value2: 25V; TaMin_C: -55; TaMax_C: 125; Cap_Case: 0603; AEC Category: Q200
C122 C128 = C1005X5R1A225K050BC: CAP, CERM, 2.2 µF, 10 V, +/- 10%, X5R, 0402; Manufacturer: TDK; Polarized: N; CompType: Capacitor; Value: 2.2uF; U/M: EA; Cap_F: 0.0000022; Tolerance_%: 10; Value1: Unknown; Value2: 10V; TaMin_C: -55; TaMax_C: 85; Cap_Case: 0402; AEC Category: Q200
C132 C133 = GRM188R71C105KA12D: CAP, CERM, 1 µF, 16 V, +/- 10%, X7R, 0603; Manufacturer: MuRata; Polarized: N; CompType: Capacitor; Value: 1uF; U/M: EA; Cap_F: 0.000001; Tolerance_%: 10; ESR_ohm: 0.011; Value1: 0.011 ohm; VDC_V: 16; Value2: 16V; TaMin_C: -55; TaMax_C: 125; Cap_Case: 0603; AEC Category: Q200
C142 = C0603C104K5RACTU: CAP, CERM, 0.1 µF, 50 V, +/- 10%, X7R, 0603; Manufacturer: Kemet; Polarized: N; CompType: Capacitor; Value: 0.1uF; U/M: EA; Cap_F: 0.0000001; Tolerance_%: 10; Value1: Unknown; VDC_V: 50; Value2: 50V; TaMin_C: -55; TaMax_C: 125; Cap_Case: 0603; AEC Category: Q200
C143 = GRM188R71H473KA61D: CAP, CERM, 0.047 µF, 50 V, +/- 10%, X7R, 0603; Manufacturer: MuRata; Polarized: N; CompType: Capacitor; Value: 0.047uF; U/M: EA; Cap_F: 0.000000047; Tolerance_%: 10; Value1: Unknown; VDC_V: 50; Value2: 50V; TaMin_C: -55; TaMax_C: 125; Cap_Case: 0603; AEC Category: Q200
J2 = N2550-6002-RB: Header(Shrouded), 2.54mm, 25x2, Gold, TH; Manufacturer: 3M; SymbolCreator: a0799628; Pitch_mm: 2.54; Gender: Male; Shrouded: Y; Row_Count: 2
JP100-JP103 = SIP3-90_PBC03SAAN: Header, 100mil, 3x1, Gold, TH; Manufacturer: Sullins Connector Solutions; Value: 1x3; U/M: EA
L100 = GLFR1608T100M-LR: Inductor, Wirewound, 10 µH, 0.08 A, 0.36 ohm, SMD; Manufacturer: TDK; Value: 10uH; Value2: 0.08A; Ind_H: 10.0E-6; Imax_A: 0.08; Irms: 0.4A @ 20C rise; Isat: 0.08A @ 10% inductance drop; DCR_ohm: 0.36; AEC Category: Q200; AEC Qualified: N
L101 L102 = UA8014-ALD: Coupled inductor, 10 µH, 6.6 A, SMD; Manufacturer: Coilcraft; SymbolCreator: a0799628; Value: 10uH; Ind_H: 1.0E-7
R17 = RC0603FR-0730KL: RES, 30.0 k, 1%, 0.1 W, 0603; Manufacturer: Yageo America; CompType: Resistor; Value: 30.0k; Res_ohm: 30000; Value_Code: 30k0; Tolerance_%: 1; Power_W: 0.1; Value2: 0.1W; VDC_V: 150; TempCo: 200 ppm/C; U/M: EA; AEC Category: Q200; SizeArea_mm2: 1.28; SizeX_mm: 1.6; SizeY_mm: 0.8
R100 = CRCW060310R0JNEA: RES, 10, 5%, 0.1 W, 0603; Manufacturer: Vishay-Dale; CompType: Resistor; Value: 10; Value_Code: 10R0; Tolerance_%: 5; Power_W: 0.1; Value2: 0.1W; VDC_V: 75; TempCo: 200 ppm/C; EIA_Code: E24; U/M: EA; AEC Category: Q200
R101 R103 R105 R107 = CRCW0603499RFKEA: RES, 499, 1%, 0.1 W, 0603; Manufacturer: Vishay-Dale; CompType: Resistor; Value: 499; Value_Code: 499R; Tolerance_%: 1; Power_W: 0.1; Value2: 0.1W; VDC_V: 75; TempCo: 100 ppm/C; EIA_Code: E96; U/M: EA; AEC Category: Q200
R102 R106 R108 R116 = CRCW0603100RFKEA: as R20 on sheet TIDA-01414_ClockDrivers
R104 R109 R118 R120 = CRCW06033R30JNEA: RES, 3.3, 5%, 0.1 W, 0603; Manufacturer: Vishay-Dale; CompType: Resistor; Value: 3.3; Value_Code: 3R30; Tolerance_%: 5; Power_W: 0.1; Value2: 0.1W; VDC_V: 75; TempCo: 200 ppm/C; EIA_Code: E24; U/M: EA; AEC Category: Q200
R110-R114 = ERJ-2RKF1002X: RES, 10.0 k, 1%, 0.1 W, 0402; Manufacturer: Panasonic; CompType: Resistor; Value: 10.0k; Res_ohm: 10000; Value_Code: 10k0; Tolerance_%: 1; Power_W: 0.1; Value2: 0.1W; VDC_V: 50; TempCo: 100 ppm/C; EIA_Code: E96; U/M: EA; AEC Category: Q200
R115 R117 = CRCW04024K99FKED: RES, 4.99 k, 1%, 0.063 W, 0402; Manufacturer: Vishay-Dale; CompType: Resistor; Value: 4.99k; Res_ohm: 4990; Value_Code: 4k99; Tolerance_%: 1; Power_W: 0.063; Value2: 0.063W; VDC_V: 50; TempCo: 100 ppm/C; EIA_Code: E96; U/M: EA; AEC Category: Q200
R119 = RC0603FR-0722KL: RES, 22.0 k, 1%, 0.1 W, 0603; Manufacturer: Yageo America; CompType: Resistor; Value: 22.0k; Res_ohm: 22000; Value_Code: 22k0; Tolerance_%: 1; Power_W: 0.1; Value2: 0.1W; VDC_V: 150; TempCo: 200 ppm/C; U/M: EA; AEC Category: Q200
SL+ SL- SR+ SR- = 63066-1: PC Quick-Fit 0.250 Tab, Vertical, TH; Manufacturer: TE Connectivity; SymbolCreator: x0221032; CompType: Quick-Fit Tab; Gender: Male; Row_Count: 1; ContactFinish: Tin
U100 = PCM5252RHBR: 4.2VRMS DirectPath™, 114dB Audio Stereo Differential-Output DAC with 32-bit, 384kHz PCM Interface, RHB0032E; Alternate PartNumber: PCM5252RHBT; Manufacturer: Texas Instruments; SymbolCreator: Altium; CompType: IC; U/M: EA
U101 = TPA3244DDWR: 40-W Stereo, 100-W peak PurePath™ Ultra-HD Pad Down Class-D Amplifier, DDW0044D; Manufacturer: Texas Instruments; SymbolCreator: Altium; SizeArea_mm2: 113.4; SizeAreaWB_mm2: 161.6; SizeX_mm: 8.1; SizeY_mm: 14; SizeZ_mm: 1.2; CompType: IC; U/M: EA
U102 U103 = SN74LVC1G125DCKR: as U4 on sheet TIDA-01414_ClockDrivers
